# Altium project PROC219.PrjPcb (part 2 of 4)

## Sheet PROC219_PLC.SchDoc
size 431 x 279 mm; Date: Not shown in title block; ApprovedBy: Not shown in title block; CheckedBy: Not shown in title block; Author: Not shown in title block; CompanyName: Not shown in title block; Engineer: Not shown in title block; Organization: Not shown in title block; Address1: Not shown in title block; Address2: Not shown in title block; Address3: Not shown in title block; Address4: Not shown in title block; DocumentNumber: 1; Revision: Use project parameter SCH_Rev; SheetNumber: 5; SheetTotal: 16; PageSetup: Record=PageOptions¦CenterHorizontal=True¦CenterVertical=True¦PrintScale=1.00¦XCorrection=1.00¦YCorrection=1.00¦PrintKind=0¦BorderSize=5000000¦LeftOffset=0¦BottomOffset=0¦Orientation=2¦PaperLength=1000¦PaperWidth=1000¦Scale=100¦PaperSource=15¦PrintQuality=600¦MediaType=1¦DitherType=10¦PaperKind=Letter¦PrintScaleMode=1
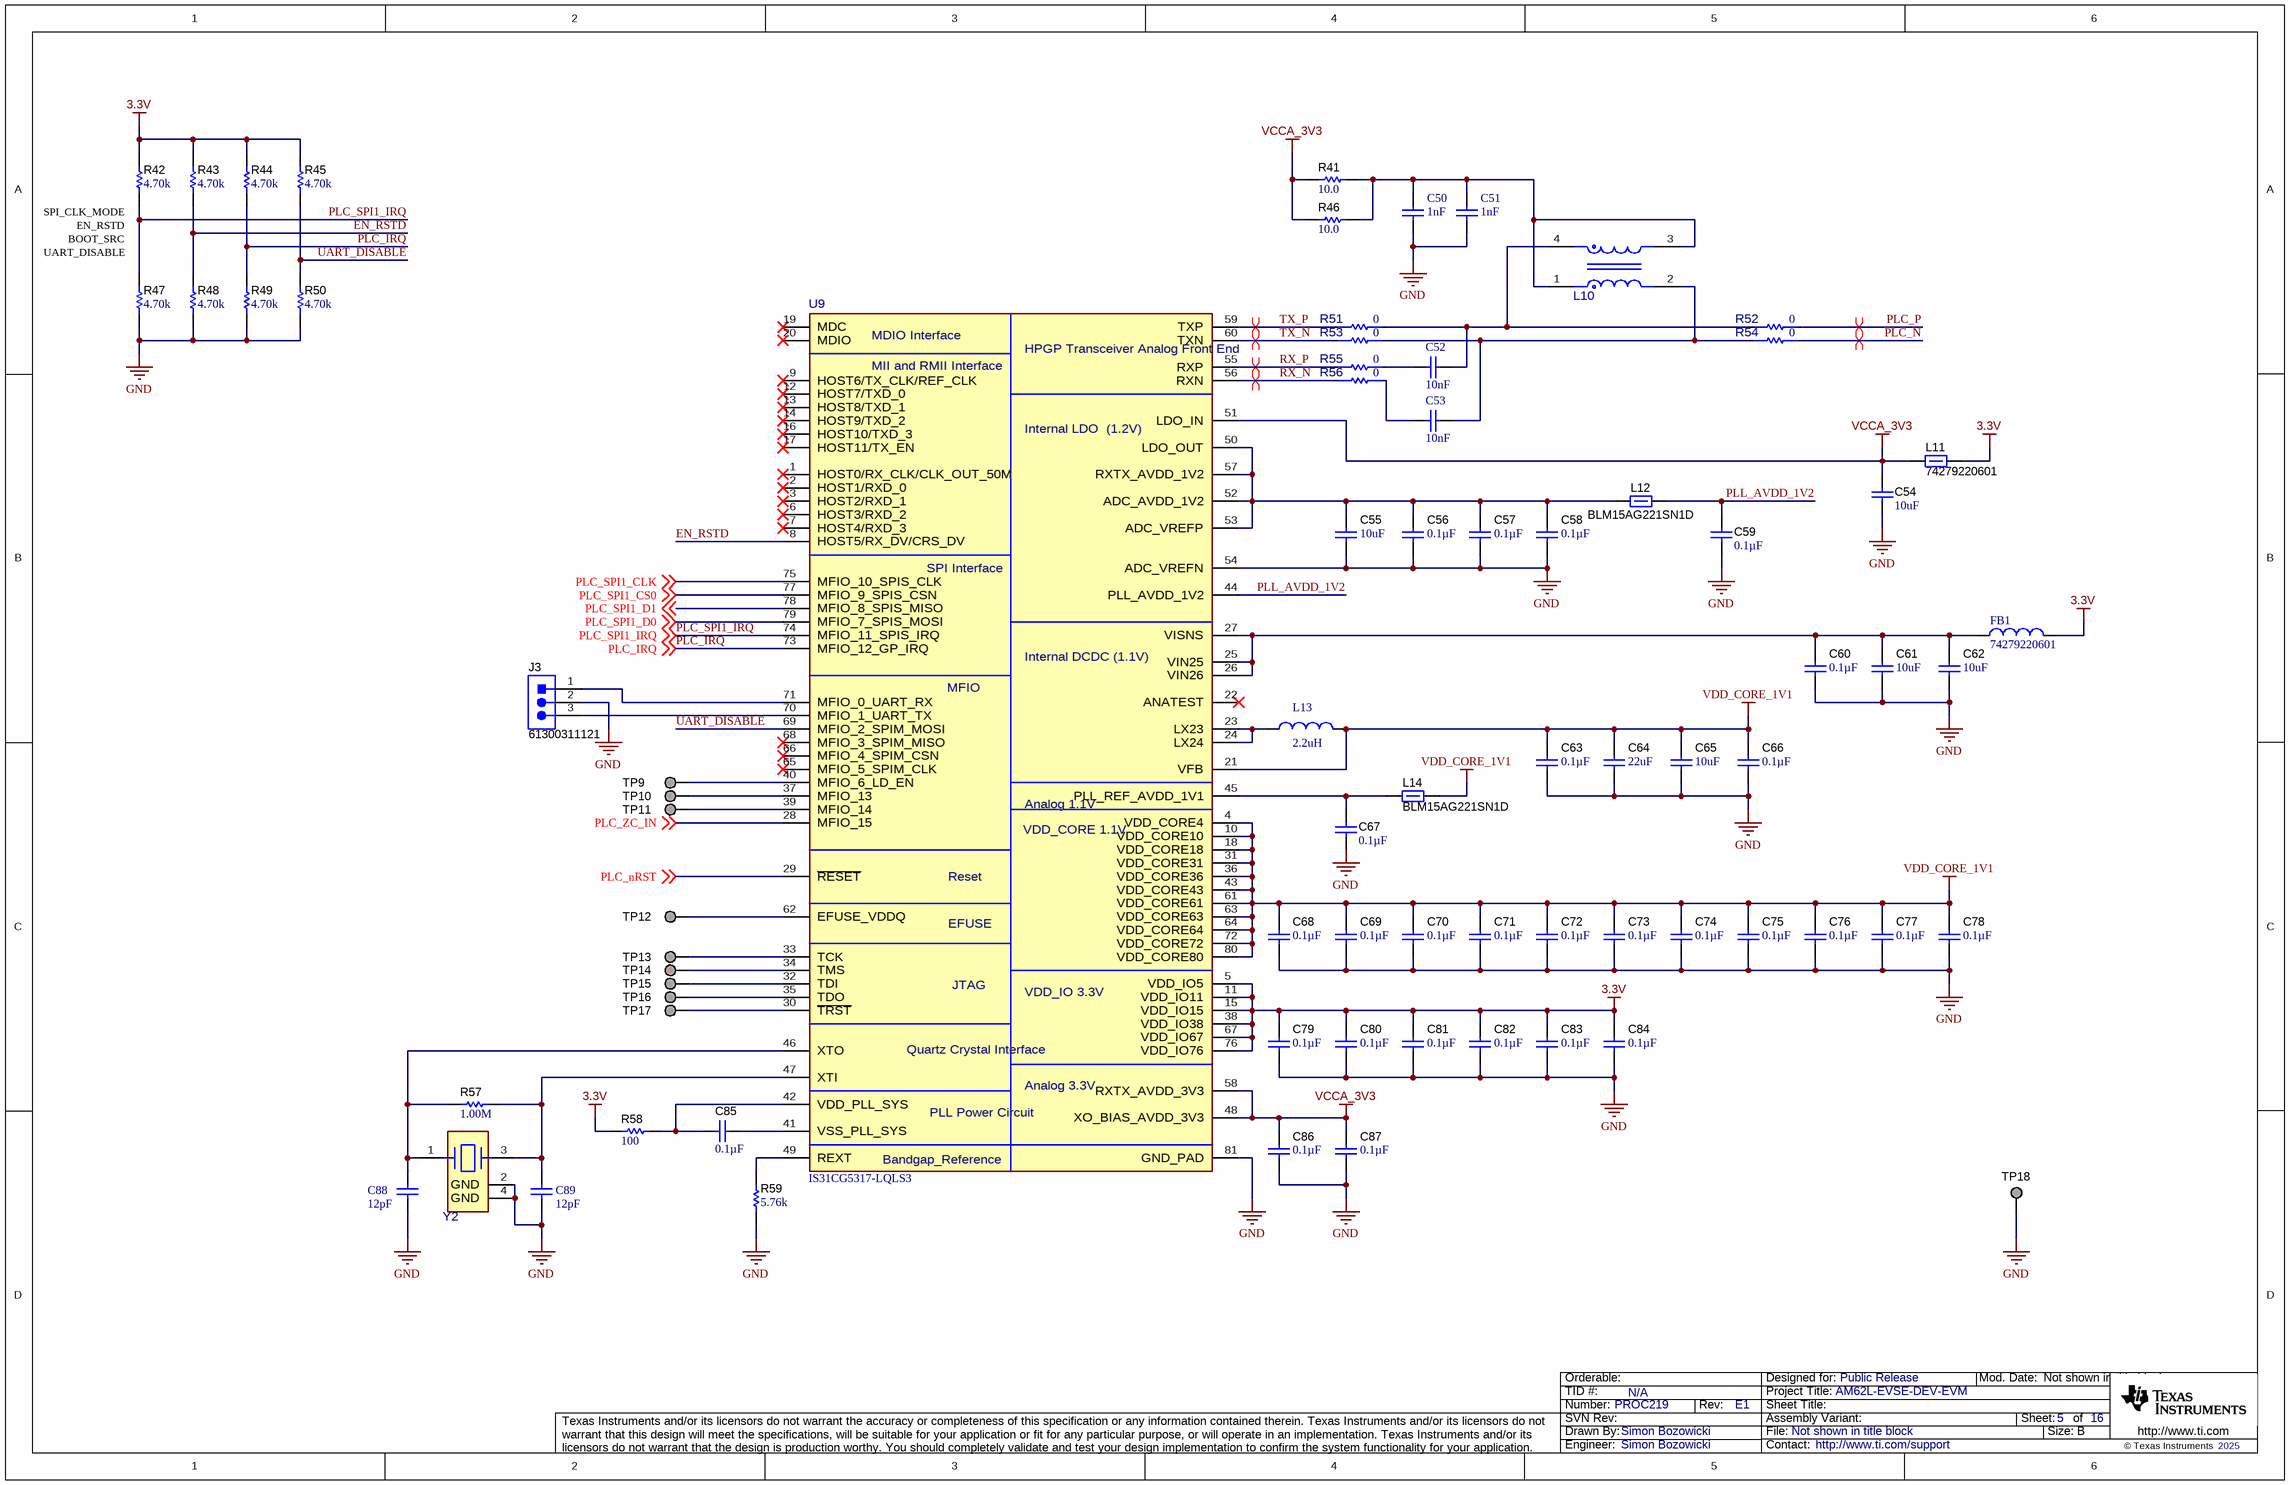
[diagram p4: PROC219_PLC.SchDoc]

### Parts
C50  value 1nF  [WCAP-CSGP_0402_L1W0.5H0.5]  (hidden comment: 885012205061)
C51  value 1nF  [WCAP-CSGP_0402_L1W0.5H0.5]  (hidden comment: 885012205061)
C52  value 10nF  [WCAP-CSGP_0402_L1W0.5H0.5]  (hidden comment: 885012205050)
C53  value 10nF  [WCAP-CSGP_0402_L1W0.5H0.5]  (hidden comment: 885012205050)
C54  ValueDisplayed: 10uF  [0603]  (hidden comment: C1608X5R1E106M080AC)
C55  ValueDisplayed: 10uF  [0603]  (hidden comment: C1608X5R1E106M080AC)
C56  ValueDisplayed: 0.1µF  [0402]  (hidden comment: CC0402KRX7R8BB104)
C57  ValueDisplayed: 0.1µF  [0402]  (hidden comment: CC0402KRX7R8BB104)
C58  ValueDisplayed: 0.1µF  [0402]  (hidden comment: CC0402KRX7R8BB104)
C59  ValueDisplayed: 0.1µF  [0402]  (hidden comment: CC0402KRX7R8BB104)
C60  ValueDisplayed: 0.1µF  [0402]  (hidden comment: CC0402KRX7R8BB104)
C61  ValueDisplayed: 10uF  [0603]  (hidden comment: C1608X5R1E106M080AC)
C62  ValueDisplayed: 10uF  [0603]  (hidden comment: C1608X5R1E106M080AC)
C63  ValueDisplayed: 0.1µF  [0402]  (hidden comment: CC0402KRX7R8BB104)
C64  ValueDisplayed: 22uF  [0805_HV]  (hidden comment: C2012X7S1A226M125AC)
C65  ValueDisplayed: 10uF  [0603]  (hidden comment: C1608X5R1E106M080AC)
C66  ValueDisplayed: 0.1µF  [0402]  (hidden comment: CC0402KRX7R8BB104)
C67  ValueDisplayed: 0.1µF  [0402]  (hidden comment: CC0402KRX7R8BB104)
C68  ValueDisplayed: 0.1µF  [0402]  (hidden comment: CC0402KRX7R8BB104)
C69  ValueDisplayed: 0.1µF  [0402]  (hidden comment: CC0402KRX7R8BB104)
C70  ValueDisplayed: 0.1µF  [0402]  (hidden comment: CC0402KRX7R8BB104)
C71  ValueDisplayed: 0.1µF  [0402]  (hidden comment: CC0402KRX7R8BB104)
C72  ValueDisplayed: 0.1µF  [0402]  (hidden comment: CC0402KRX7R8BB104)
C73  ValueDisplayed: 0.1µF  [0402]  (hidden comment: CC0402KRX7R8BB104)
C74  ValueDisplayed: 0.1µF  [0402]  (hidden comment: CC0402KRX7R8BB104)
C75  ValueDisplayed: 0.1µF  [0402]  (hidden comment: CC0402KRX7R8BB104)
C76  ValueDisplayed: 0.1µF  [0402]  (hidden comment: CC0402KRX7R8BB104)
C77  ValueDisplayed: 0.1µF  [0402]  (hidden comment: CC0402KRX7R8BB104)
C78  ValueDisplayed: 0.1µF  [0402]  (hidden comment: CC0402KRX7R8BB104)
C79  ValueDisplayed: 0.1µF  [0402]  (hidden comment: CC0402KRX7R8BB104)
C80  ValueDisplayed: 0.1µF  [0402]  (hidden comment: CC0402KRX7R8BB104)
C81  ValueDisplayed: 0.1µF  [0402]  (hidden comment: CC0402KRX7R8BB104)
C82  ValueDisplayed: 0.1µF  [0402]  (hidden comment: CC0402KRX7R8BB104)
C83  ValueDisplayed: 0.1µF  [0402]  (hidden comment: CC0402KRX7R8BB104)
C84  ValueDisplayed: 0.1µF  [0402]  (hidden comment: CC0402KRX7R8BB104)
C85  ValueDisplayed: 0.1µF  [0402]  (hidden comment: CC0402KRX7R8BB104)
C86  ValueDisplayed: 0.1µF  [0402]  (hidden comment: CC0402KRX7R8BB104)
C87  ValueDisplayed: 0.1µF  [0402]  (hidden comment: CC0402KRX7R8BB104)
C88  value 12pF  [WCAP-CSRF_0402_L1W0.5H0.5]  (hidden comment: 885392005127)
C89  value 12pF  [WCAP-CSRF_0402_L1W0.5H0.5]  (hidden comment: 885392005127)
FB1  74279220601  [WE-MPSB_0805_L2W1.2H0.9]
J3  61300311121  [WURTH_61300311121]
L10  DLW43SH110XK2L  [FP-DLW43SH110XK2L_1812-MFG]  (value not drawn)
L11  74279220601  [0805_HV]
L12  BLM15AG221SN1D  [0402]
L13  value 2.2uH  [WE-PMCI_1210_L3.2W2.5H1.2]  (hidden comment: 74479299222)
L14  BLM15AG221SN1D  [0402]
R41  ValueDisplayed: 10.0  [0603]  (hidden comment: RC0603FR-0710RL)
R42  ValueDisplayed: 4.70k  [0402]  (hidden comment: ERJ-2RKF4701X)
R43  ValueDisplayed: 4.70k  [0402]  (hidden comment: ERJ-2RKF4701X)
R44  ValueDisplayed: 4.70k  [0402]  (hidden comment: ERJ-2RKF4701X)
R45  ValueDisplayed: 4.70k  [0402]  (hidden comment: ERJ-2RKF4701X)
R46  ValueDisplayed: 10.0  [0603]  (hidden comment: RC0603FR-0710RL)
R47  ValueDisplayed: 4.70k  [0402]  (hidden comment: ERJ-2RKF4701X)
R48  ValueDisplayed: 4.70k  [0402]  (hidden comment: ERJ-2RKF4701X)
R49  ValueDisplayed: 4.70k  [0402]  (hidden comment: ERJ-2RKF4701X)
R50  ValueDisplayed: 4.70k  [0402]  (hidden comment: ERJ-2RKF4701X)
R51  value 0  [FP-CRG0402ZR_0402-IPC_C]  (hidden comment: CRG0402ZR)
R52  value 0  [FP-CRG0402ZR_0402-IPC_C]  (hidden comment: CRG0402ZR)
R53  value 0  [FP-CRG0402ZR_0402-IPC_C]  (hidden comment: CRG0402ZR)
R54  value 0  [FP-CRG0402ZR_0402-IPC_C]  (hidden comment: CRG0402ZR)
R55  value 0  [FP-CRG0402ZR_0402-IPC_C]  (hidden comment: CRG0402ZR)
R56  value 0  [FP-CRG0402ZR_0402-IPC_C]  (hidden comment: CRG0402ZR)
R57  ValueDisplayed: 1.00M  [0402]  (hidden comment: RC0402FR-071ML)
R58  ValueDisplayed: 100  [0402]  (hidden comment: ERJ-2RKF1000X)
R59  ValueDisplayed: 5.76k  [0402]  (hidden comment: CRCW04025K76FKED)
TP9  TP_SM_1MM  [TP_SM_1MM]  (value not drawn)  (no BOM)
TP10  TP_SM_1MM  [TP_SM_1MM]  (value not drawn)  (no BOM)
TP11  TP_SM_1MM  [TP_SM_1MM]  (value not drawn)  (no BOM)
TP12  TP_SM_1MM  [TP_SM_1MM]  (value not drawn)  (no BOM)
TP13  TP_SM_1MM  [TP_SM_1MM]  (value not drawn)  (no BOM)
TP14  TP_SM_1MM  [TP_SM_1MM]  (value not drawn)  (no BOM)
TP15  TP_SM_1MM  [TP_SM_1MM]  (value not drawn)  (no BOM)
TP16  TP_SM_1MM  [TP_SM_1MM]  (value not drawn)  (no BOM)
TP17  TP_SM_1MM  [TP_SM_1MM]  (value not drawn)  (no BOM)
TP18  TP_SM_1MM  [TP_SM_1MM]  (value not drawn)  (no BOM)
U9  IS31CG5317-LQLS3  [FP-IS31CG5317-LQLS3_LQFP80-MFG]
Y2  ABM8W-25.0000MHZ-8-D1X-T3  [FP-ABM8W-25.0000MHZ-8-D1X-T3_SMD4-MFG]  (value not drawn)

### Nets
3.3V: C79.1 C80.1 C81.1 C82.1 C83.1 C84.1 FB1.2 L11.2 R42.2 R43.2 R44.2 R45.2 R58.2 U9.5(VDD_IO5) U9.11(VDD_IO11) U9.15(VDD_IO15) U9.38(VDD_IO38) U9.67(VDD_IO67) U9.76(VDD_IO76)
GND: C50.2 C51.2 C54.1 C55.2 C56.2 C57.2 C58.2 C59.1 C60.2 C61.2 C62.2 C63.2 C64.2 C65.2 C66.2 C67.2 C68.2 C69.2 C70.2 C71.2 C72.2 C73.2 C74.2 C75.2 C76.2 C77.2 C78.2 C79.2 C80.2 C81.2 C82.2 C83.2 C84.2 C86.2 C87.2 C88.1 C89.1 J3.2 R47.1 R48.1 R49.1 R50.1 R59.1 TP18.1 U9.54(ADC_VREFN) U9.81(GND_PAD) Y2.2(GND) Y2.4(GND)
VCCA_3V3: C54.2 C86.1 C87.1 L11.1 R41.1 R46.1 U9.48(XO_BIAS_AVDD_3V3) U9.51(LDO_IN) U9.58(RXTX_AVDD_3V3)
VDD_CORE_1V1: C63.1 C64.1 C65.1 C66.1 C68.1 C69.1 C70.1 C71.1 C72.1 C73.1 C74.1 C75.1 C76.1 C77.1 C78.1 L13.2 L14.2 U9.4(VDD_CORE4) U9.10(VDD_CORE10) U9.18(VDD_CORE18) U9.21(VFB) U9.31(VDD_CORE31) U9.36(VDD_CORE36) U9.43(VDD_CORE43) U9.61(VDD_CORE61) U9.63(VDD_CORE63) U9.64(VDD_CORE64) U9.72(VDD_CORE72) U9.80(VDD_CORE80)
EN_RSTD: R43.1 R48.2 U9.8(HOST5/RX_DV/CRS_DV)
PLC_IRQ: R44.1 R49.2 U9.73(MFIO_12_GP_IRQ) ; off-sheet PLC_IRQ
PLC_N: R54.1
PLC_nRST: U9.29(~{RESET}) ; off-sheet PLC_nRST
PLC_P: R52.1
PLC_SPI1_CLK: U9.75(MFIO_10_SPIS_CLK) ; off-sheet PLC_SPI1_CLK
PLC_SPI1_CS0: U9.77(MFIO_9_SPIS_CSN) ; off-sheet PLC_SPI1_CS0
PLC_SPI1_D0: U9.79(MFIO_7_SPIS_MOSI) ; off-sheet PLC_SPI1_D0
PLC_SPI1_D1: U9.78(MFIO_8_SPIS_MISO) ; off-sheet PLC_SPI1_D1
PLC_SPI1_IRQ: R42.1 R47.2 U9.74(MFIO_11_SPIS_IRQ) ; off-sheet PLC_SPI1_IRQ
PLC_ZC_IN: U9.28(MFIO_15) ; off-sheet PLC_ZC_IN
PLL_AVDD_1V2: C59.2 L12.2 U9.44(PLL_AVDD_1V2)
RX_N: R56.2 U9.56(RXN)
RX_P: R55.2 U9.55(RXP)
TX_N: R53.2 U9.60(TXN)
TX_P: R51.2 U9.59(TXP)
UART_DISABLE: R45.1 R50.2 U9.69(MFIO_2_SPIM_MOSI)
NetC50_1: C50.1 C51.1 L10.1 L10.3 R41.2 R46.2
NetC52_1: C52.1 L10.4 R51.1 R52.2
NetC52_2: C52.2 R55.1
NetC53_1: C53.1 L10.2 R53.1 R54.2
NetC53_2: C53.2 R56.1
NetC55_1: C55.1 C56.1 C57.1 C58.1 L12.1 U9.50(LDO_OUT) U9.52(ADC_AVDD_1V2) U9.53(ADC_VREFP) U9.57(RXTX_AVDD_1V2)
NetC60_1: C60.1 C61.1 C62.1 FB1.1 U9.25(VIN25) U9.26(VIN26) U9.27(VISNS)
NetC67_1: C67.1 L14.1 U9.45(PLL_REF_AVDD_1V1)
NetC85_1: C85.1 U9.41(VSS_PLL_SYS)
NetC85_2: C85.2 R58.1 U9.42(VDD_PLL_SYS)
NetC88_2: C88.2 R57.1 U9.46(XTO) Y2.1
NetC89_2: C89.2 R57.2 U9.47(XTI) Y2.3
NetJ3_1: J3.1 U9.71(MFIO_0_UART_RX)
NetJ3_3: J3.3 U9.70(MFIO_1_UART_TX)
NetL13_1: L13.1 U9.23(LX23) U9.24(LX24)
NetR59_2: R59.2 U9.49(REXT)
NetTP9_1: TP9.1 U9.40(MFIO_6_LD_EN)
NetTP10_1: TP10.1 U9.37(MFIO_13)
NetTP11_1: TP11.1 U9.39(MFIO_14)
NetTP12_1: TP12.1 U9.62(EFUSE_VDDQ)
NetTP13_1: TP13.1 U9.33(TCK)
NetTP14_1: TP14.1 U9.34(TMS)
NetTP15_1: TP15.1 U9.32(TDI)
NetTP16_1: TP16.1 U9.35(TDO)
NetTP17_1: TP17.1 U9.30(~{TRST})

Not connected (* = marked no-connect by the designer): U9 1(HOST0/RX_CLK/CLK_OUT_50M)* 2(HOST1/RXD_0)* 3(HOST2/RXD_1)* 6(HOST3/RXD_2)* 7(HOST4/RXD_3)* 9(HOST6/TX_CLK/REF_CLK)* 12(HOST7/TXD_0)* 13(HOST8/TXD_1)* 14(HOST9/TXD_2)* 16(HOST10/TXD_3)* 17(HOST11/TX_EN)* 19(MDC)* 20(MDIO)* 22(ANATEST)* 65(MFIO_5_SPIM_CLK)* 66(MFIO_4_SPIM_CSN)* 68(MFIO_3_SPIM_MISO)*

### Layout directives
differential pair: PLC_N, PLC_P, RX_N, RX_P, TX_N, TX_P

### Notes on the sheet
- (near R42) SPI_CLK_MODE
- (near R42) EN_RSTD
- BOOT_SRC
- (near R47) UART_DISABLE

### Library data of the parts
C50 C51 = CMP-0115372-1: WCAP-CSGP Multilayer Ceramic Chip Capacitor, General Purpose, size 0402, X7R, 1nF, 50VDC; Manufacturer: Wurth Elektronik; Capacitance Tolerance: +/-10%; Dissipation Factor: 2.5%; Insulation Resistance: 10GOhm; Rated Voltage (DC): 50V; Technical Reference: X7R0402102K050DFCT10000
C52 C53 = CMP-0052806-1: WCAP-CSGP Multilayer Ceramic Chip Capacitor, General Purpose, size 0402, X7R, 10nF, 25VDC; Manufacturer: Wurth Elektronik; Capacitance Tolerance: +/-10%; Dissipation Factor: 3.5%; Insulation Resistance: 10GOhm; Rated Voltage (DC): 25V; Technical Reference: X7R0402103K025DFCT10000
C54 C55 C61 C62 C65 = CMP-0007007-5: CAP, CERM, 10 uF, 25 V, +/- 20%, X5R, 0603; Manufacturer: TDK; TaMin_C: -55°C; ESR_ohm: 4.639m; Polarized: N; SizeAreaWB_mm2: 4.68; Value1: 0.004639 ohm; U/M: EA; Value: 10uF; TaMax_C: 85°C; SizeZ_mm: 1; SizeX_mm: 1.6; SizeY_mm: 0.8; Value2: 25V; SizeArea_mm2: 1.28; Cap_F: 10µF; IRMS_A: 2.41407A; AEC Category: Q200
C56-C60 C63 C66-C87 = CMP-0860555-1: CAP, CERM, 0.1 µF, 25 V,+/- 10%, X7R, 0402; Manufacturer: Yageo; SizeArea_mm2: 0.5; AEC Qualified: N; SizeX_mm: 1; U/M: EA; Value: 0.1uF; TaMin_C: -55°C; VDC_V: 25V; SizeZ_mm: 0.6; Cap_F: 100nF; TaMax_C: 125°C; SizeAreaWB_mm2: 3; AEC Category: Q200
C64 = CMP-0007890-2: CAP, CERM, 22 uF, 10 V, +/- 20%, X7S, 0805; Manufacturer: TDK; TaMin_C: -55°C; ESR_ohm: 2.05m; Polarized: N; SizeAreaWB_mm2: 6.75; Value1: 0.00205 ohm; U/M: EA; Value: 22uF; TaMax_C: 125°C; SizeZ_mm: 1.45; SizeX_mm: 2; SizeY_mm: 1.25; Cap_Case: 0805; Value2: 10V; SizeArea_mm2: 2.5; Cap_F: 22µF; IRMS_A: 4.55587A; AEC Category: Q200
C88 C89 = CMP-0105275-1: WCAP-CSRF Multilayer Ceramic Chip Capacitor, High Frequency, size 0402, NP0 Class I, 12pF, 50VDC; Manufacturer: Wurth Elektronik; Capacitance Tolerance: +/-2%; Insulation Resistance: 10GOhm; Q Factor: 640; Rated Voltage (DC): 50V; Technical Reference: NP00402120G050DFCT1R000
FB1 = CMP-03913-52738340-1: 74279220601 Ferrite Beads Multi-Layer High Current 600Ohm 25% 100MHz 2.1A 0.08Ohm DCR 0805 Automotive T/R; Manufacturer: Wurth Elektronik; DC Resistance (DCR): 43mΩ; Number of Lines: 1; Value: 600Ω
J3 = CMP-0054796-4: Header, 2.54 mm, 3x1, Gold, TH; Manufacturer: Wurth Elektronik; Green_REACh: Passed; CT: FALSE; CNHeader: TRUE; Green_Lifecycle: Active
L10 = CMP-0124832-1: 2 Line Common Mode Choke Surface Mount 360mA DCR 500mOhm; Manufacturer: Murata; AEC Grade: Grade 1; AEC Qualified: Yes; DCR_ohm: 0.5; Ind_H: 11µH; SizeZ_mm: 2.8mm; Shrouded: true; Test Frequency: 100kHz; Tolerance_%: +50/-30%
L11 = CMP-0003136-1: Ferrite Bead, 600 ohm @ 100 MHz, 2.1 A, 0805; Manufacturer: Wurth Elektronik; Ztyp@1GHz_Ohm: 101.062; ZTyp@100MHz_Ohm: 600; SizeAreaWB_mm2: 6.75; DCR_ohm: 0.043; Value1: 0.043 ohm; Value: 600 ohm; Imax_A: 2.1A; SizeZ_mm: 1.45; SizeX_mm: 2; SizeY_mm: 1.25; SizeArea_mm2: 2.5
L12 L14 = CMP-0003312-1: Ferrite Bead, 220 ohm @ 100 MHz, 0.45 A, 0402; Manufacturer: MuRata; ZTyp@100MHz_Ohm: 220; SizeAreaWB_mm2: 3; DCR_ohm: 2.9d; Value1: 0.29 ohm; Value: 220 ohm; Imax_A: 4.5dA; SizeZ_mm: 0.6; SizeX_mm: 1; SizeY_mm: 0.5; Value2: 0.45A
L13 = CMP-0100963-1: WE-PMCI SMT Power Molded Chip Inductor, size 1210, 2.2uH, 4.5A, 75mOhm; Manufacturer: Wurth Elektronik; DC Resistance: 70mOhm; Saturation Current: 4.8A; Self Resonant Frequency: 35MHz; Type: High Saturation Current
R41 R46 = CMP-0022751-4: RES, 10.0, 1%, 0.1 W, 0603; Manufacturer: Yageo; Power_W: 100mW; TempCo: 100 ppm/C; Value_Code: 10R0; Value: 10.0; EIA_Code: E96; Res_ohm: 10; SizeX_mm: 1.6; SizeY_mm: 0.8; SizeZ_mm: 1; Value2: 0.1W; SizeArea_mm2: 1.28; AEC Qualified: N; VDC_V: 75V; AEC Category: Q200; SizeAreaWB_mm2: 4.68
R42-R45 R47-R50 = CMP-0026700-1: RES, 4.70 k, 1%, 0.1 W, 0402; Manufacturer: Panasonic; Power_W: 100mW; TempCo: 100 ppm/C; Value_Code: 4k70; U/M: EA; Value: 4.70k; Res_ohm: 4.7k; SizeX_mm: 1; SizeY_mm: 0.5; SizeZ_mm: 0.6; Value2: 0.1W; VDC_V: 50V; AEC Category: Q200
R51-R56 = CMP-0095664-1: Jumper 0.063W, 1/16W Chip Resistor 0402 (1005 Metric) - Thick Film; Manufacturer: TE Connectivity; SizeZ_mm: 0.4mm; VDC_V: 50V; TempCo: 200ppm/°C; Power_W: 62.5mW; AEC Qualified: No
R57 = CMP-0026727-1: RES, 1.00 M, 1%, 0.063 W, 0402; Manufacturer: Yageo America; Power_W: 63mW; TempCo: 100 ppm/C; Value_Code: 1M00; U/M: EA; Value: 1.00Meg; EIA_Code: E96; Res_ohm: 1M; SizeX_mm: 1; SizeY_mm: 0.5; SizeZ_mm: 0.6; Value2: 0.063W; AEC Category: Q200
R58 = CMP-0026656-1: RES, 100, 1%, 0.1 W, 0402; Manufacturer: Panasonic; Power_W: 100mW; TempCo: 100 ppm/C; Value_Code: 100R; U/M: EA; Value: 100; EIA_Code: E96; SizeX_mm: 1; SizeY_mm: 0.5; SizeZ_mm: 0.6; Value2: 0.1W; VDC_V: 50V; AEC Category: Q200
R59 = CMP-0026468-2: RES, 5.76 k, 1%, 0.063 W, AEC-Q200 Grade 0, 0402; Manufacturer: Vishay-Dale; Power_W: 63mW; TempCo: 100 ppm/C; Value_Code: 5k76; Value: 5.76k; EIA_Code: E96; SizeX_mm: 1; SizeY_mm: 0.5; SizeZ_mm: 0.6; Value2: 0.063W; AEC Qualified: Y; VDC_V: 50V; AEC Category: Q200; AEC Grade: 0
TP9-TP18 = CMP-0003825-1: 1mm Test Point, SMT; Manufacturer: Any
U9 = CMP-0124871-1: Manufacturer: Lumissil Microsystems; SizeZ_mm: 1.6mm; Standoff Height: 0.05mm
Y2 = CMP-0124828-1: Crystal 25MHz ±10ppm (Tol) ±20ppm (Stability) 8pF FUND 100Ohm 4-Pin SMD T/R; Manufacturer: Abracon; SizeZ_mm: 0.75mm; AEC Qualified: No; Esr: 50

## Sheet PROC219_Pilot_Interface.SchDoc
size 431 x 279 mm; Date: Not shown in title block; ApprovedBy: Not shown in title block; CheckedBy: Not shown in title block; Author: Not shown in title block; CompanyName: Not shown in title block; Engineer: Not shown in title block; Organization: Not shown in title block; Address1: Not shown in title block; Address2: Not shown in title block; Address3: Not shown in title block; Address4: Not shown in title block; DocumentNumber: 1; Revision: Use project parameter SCH_Rev; SheetNumber: 6; SheetTotal: 16; PageSetup: Record=PageOptions¦CenterHorizontal=True¦CenterVertical=True¦PrintScale=1.00¦XCorrection=1.00¦YCorrection=1.00¦PrintKind=0¦BorderSize=5000000¦LeftOffset=0¦BottomOffset=0¦Orientation=2¦PaperLength=1000¦PaperWidth=1000¦Scale=100¦PaperSource=15¦PrintQuality=600¦MediaType=1¦DitherType=10¦PaperKind=Letter¦PrintScaleMode=1
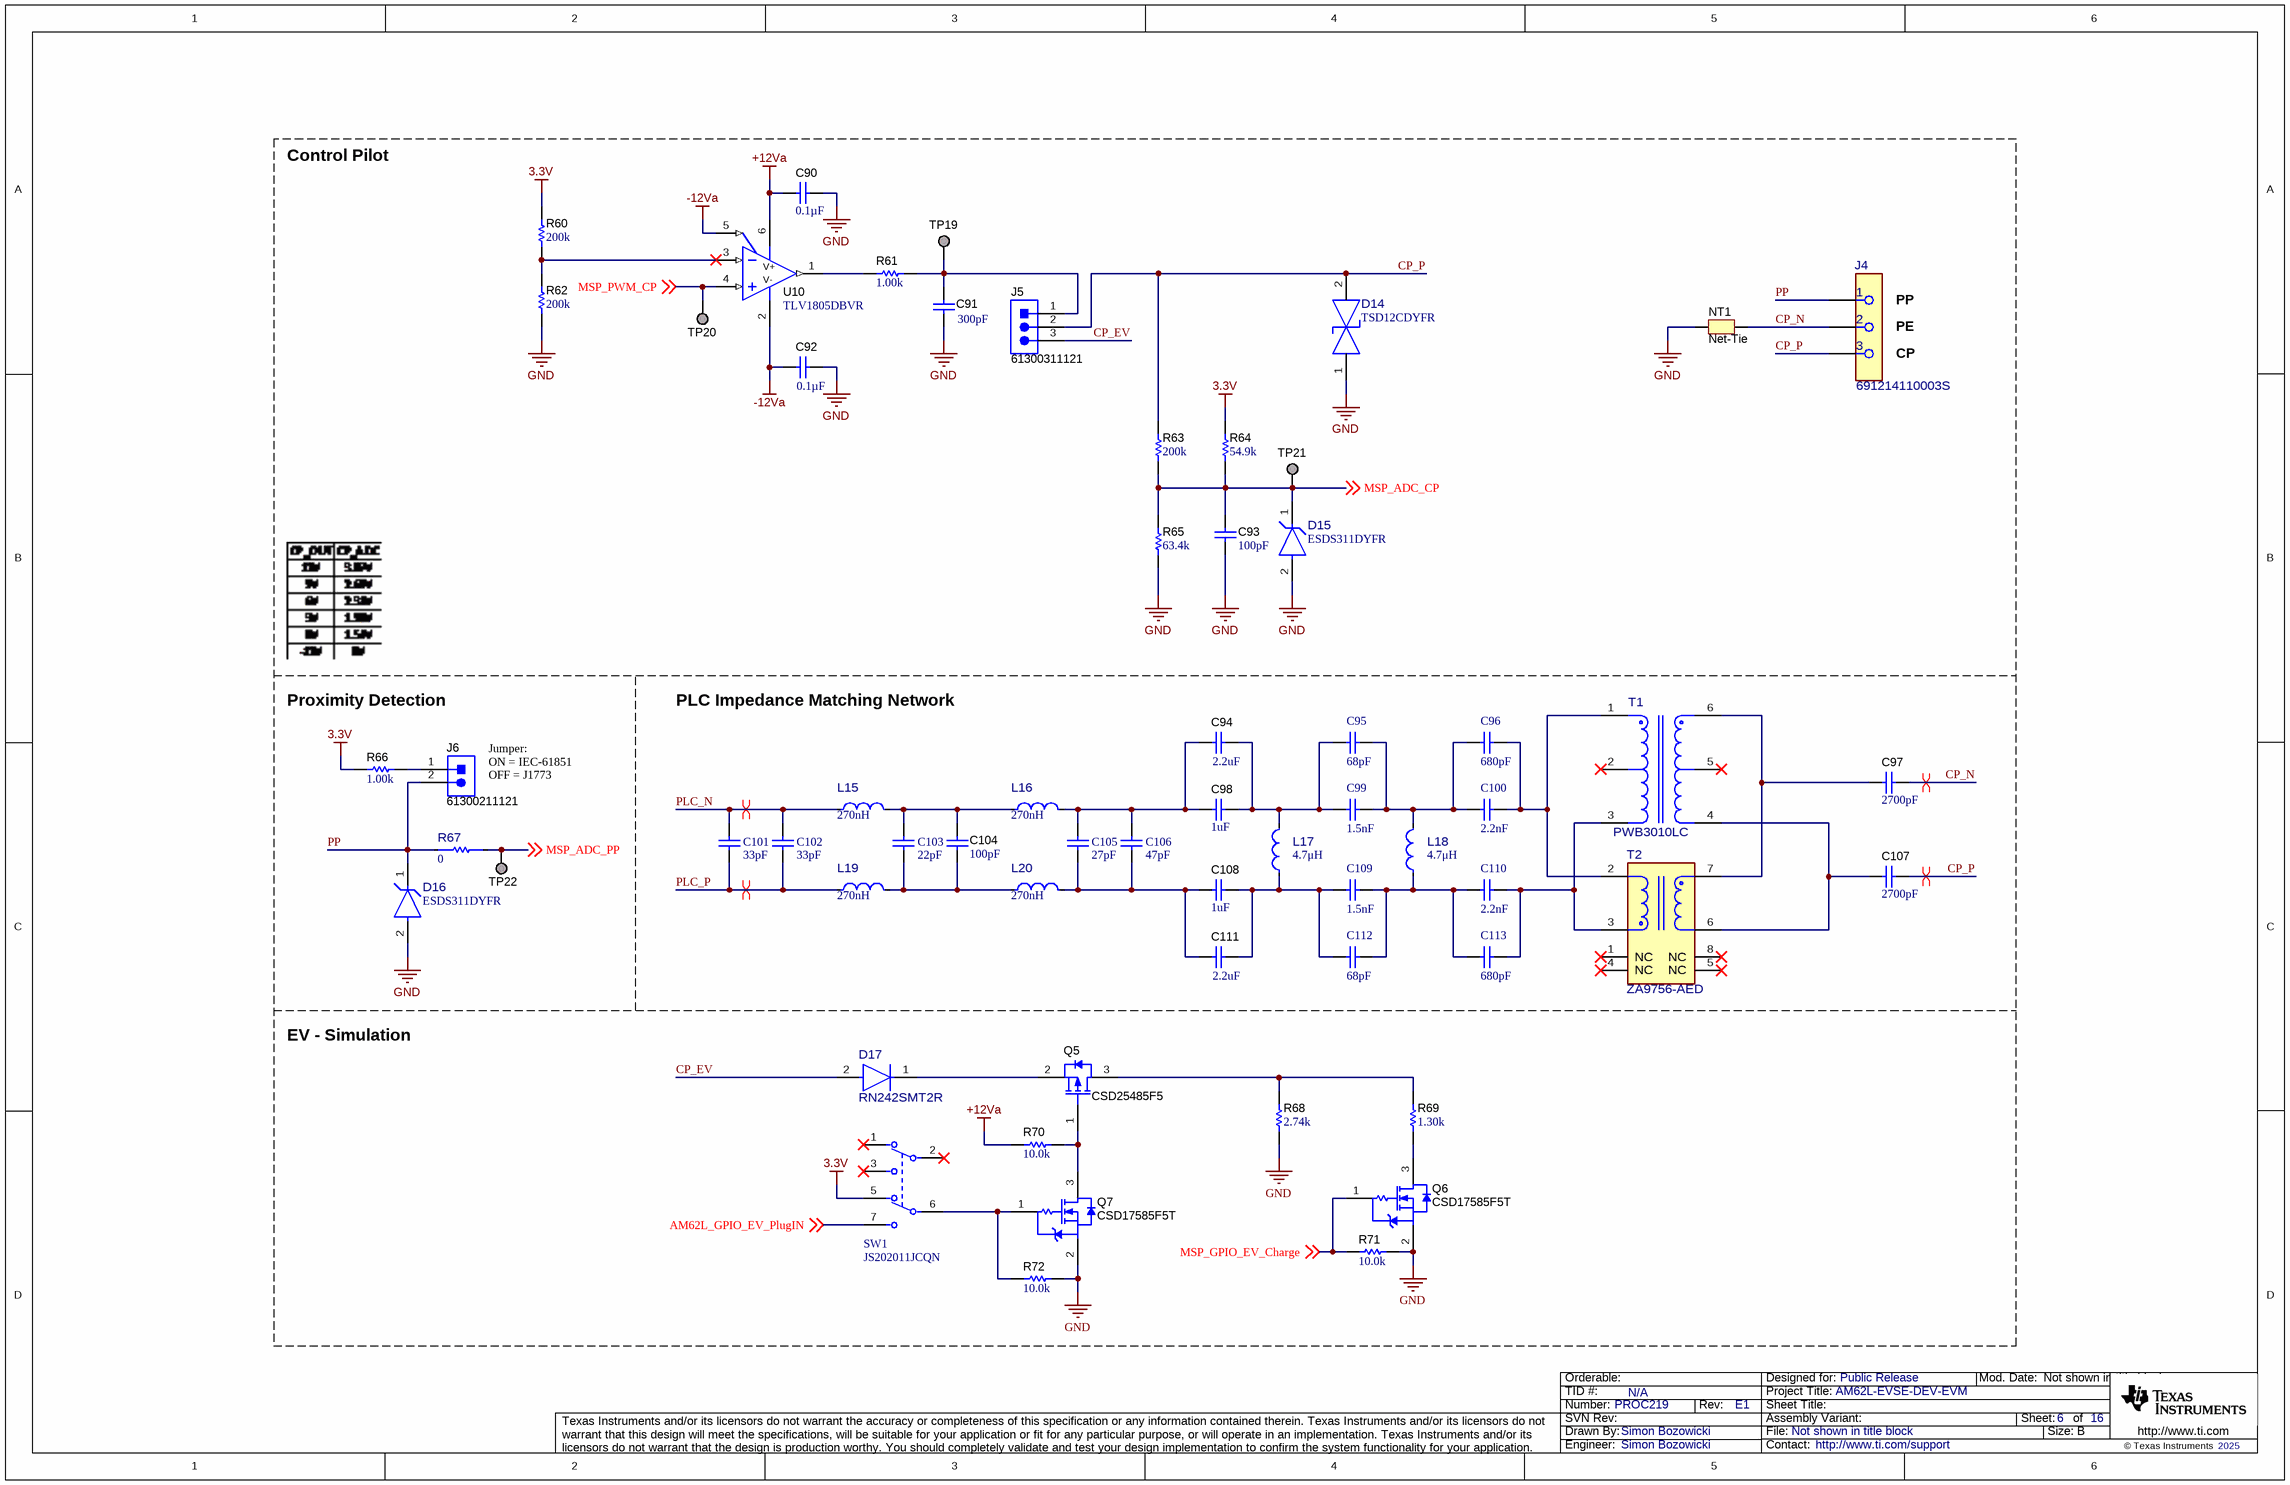
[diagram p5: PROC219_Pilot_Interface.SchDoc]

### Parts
C90  ValueDisplayed: 0.1µF  [0402]  (hidden comment: CC0402KRX7R8BB104)
C91  ValueDisplayed: 300pF  [0402]  (hidden comment: GCM1555C1H301JA16D)
C92  ValueDisplayed: 0.1µF  [0402]  (hidden comment: CC0402KRX7R8BB104)
C93  ValueDisplayed: 100pF  [0402]  (hidden comment: 04025A101FAT2A)
C94  ValueDisplayed: 2.2uF  [0402]  (hidden comment: C1005X5R1C225K050BC)
C95  value 68pF  [WCAP-CSGP_0402_L1W0.5H0.5]  (hidden comment: 885012005060)
C96  value 680pF  [WCAP-CSGP_0402_L1W0.5H0.5]  (hidden comment: 885012205060)
C97  ValueDisplayed: 2700pF  [0402]  (hidden comment: CL05B272KB5NNNC)
C98  ValueDisplayed: 1uF  [0402]  (hidden comment: C1005X7S1A105K050BC)
C99  value 1.5nF  [WCAP-CSGP_0402_L1W0.5H0.5]  (hidden comment: 885012205062)
C100  value 2.2nF  [WCAP-CSGP_0402_L1W0.5H0.5]  (hidden comment: 885012205063)
C101  value 33pF  [WCAP-CSGP_0402_L1W0.5H0.5]  (hidden comment: 885012005058)
C102  value 33pF  [WCAP-CSGP_0402_L1W0.5H0.5]  (hidden comment: 885012005058)
C103  value 22pF  [WCAP-CSRF_0402_L1W0.5H0.5]  (hidden comment: 885392005114)
C104  ValueDisplayed: 100pF  [0402]  (hidden comment: 04025A101FAT2A)
C105  value 27pF  [WCAP-CSRF_0402_L1W0.5H0.5]  (hidden comment: 885392005116)
C106  value 47pF  [WCAP-CSGP_0402_L1W0.5H0.5]  (hidden comment: 885012005059)
C107  ValueDisplayed: 2700pF  [0402]  (hidden comment: CL05B272KB5NNNC)
C108  ValueDisplayed: 1uF  [0402]  (hidden comment: C1005X7S1A105K050BC)
C109  value 1.5nF  [WCAP-CSGP_0402_L1W0.5H0.5]  (hidden comment: 885012205062)
C110  value 2.2nF  [WCAP-CSGP_0402_L1W0.5H0.5]  (hidden comment: 885012205063)
C111  ValueDisplayed: 2.2uF  [0402]  (hidden comment: C1005X5R1C225K050BC)
C112  value 68pF  [WCAP-CSGP_0402_L1W0.5H0.5]  (hidden comment: 885012005060)
C113  value 680pF  [WCAP-CSGP_0402_L1W0.5H0.5]  (hidden comment: 885012205060)
D14  TSD12CDYFR  [DYF0002A-CA-MFG]
D15  ESDS311DYFR  [DYF0002A-MFG]
D16  ESDS311DYFR  [DYF0002A-MFG]
D17  RN242SMT2R  [FP-RN242SMT2R_EMD2-MFG]
J4  691214110003S  [FP-691214110003S_CONN_TERM_BLK_3-MFG]
J5  61300311121  [WURTH_61300311121]
J6  61300211121  [WURTH_61300211121]
L15  value 270nH  [FP-LQW18ANR27G80D_0603 (1608)-MFG]  (hidden comment: LQW18ANR27G80D)
L16  value 270nH  [FP-LQW18ANR27G80D_0603 (1608)-MFG]  (hidden comment: LQW18ANR27G80D)
L17  value 4.7μH  [FP-LQM21PN4R7MGRD_0805 (2012)-MFG]  (hidden comment: LQM21PN4R7MGRD)
L18  value 4.7μH  [FP-LQM21PN4R7MGRD_0805 (2012)-MFG]  (hidden comment: LQM21PN4R7MGRD)
L19  value 270nH  [FP-LQW18ANR27G80D_0603 (1608)-MFG]  (hidden comment: LQW18ANR27G80D)
L20  value 270nH  [FP-LQW18ANR27G80D_0603 (1608)-MFG]  (hidden comment: LQW18ANR27G80D)
NT1  Net-Tie  [Net-Tie_10mil]  (net tie, no BOM)
Q5  CSD25485F5  [YJK0003A]
Q6  CSD17585F5T  [YJK0003A]
Q7  CSD17585F5T  [YJK0003A]
R60  ValueDisplayed: 200k  [0402]  (hidden comment: ERJ-2RKF2003X)
R61  ValueDisplayed: 1.00k  [0805_HV]  (hidden comment: RP73PF2A1K0BTDF)
R62  ValueDisplayed: 200k  [0402]  (hidden comment: ERJ-2RKF2003X)
R63  ValueDisplayed: 200k  [0402]  (hidden comment: ERJ-2RKF2003X)
R64  ValueDisplayed: 54.9k  [0402]  (hidden comment: CRCW040254K9FKED)
R65  ValueDisplayed: 63.4k  [0402]  (hidden comment: CRCW040263K4FKED)
R66  ValueDisplayed: 1.00k  [0402]  (hidden comment: RC0402FR-071KL)
R67  value 0  [FP-CRG0402ZR_0402-IPC_C]  (hidden comment: CRG0402ZR)
R68  ValueDisplayed: 2.74k  [0402]  (hidden comment: CRCW04022K74FKED)
R69  ValueDisplayed: 1.30k  [0402]  (hidden comment: CRCW04021K30FKED)
R70  ValueDisplayed: 10.0k  [0402]  (hidden comment: ERJ-2RKF1002X)
R71  ValueDisplayed: 10.0k  [0402]  (hidden comment: ERJ-2RKF1002X)
R72  ValueDisplayed: 10.0k  [0402]  (hidden comment: ERJ-2RKF1002X)
SW1  JS202011JCQN  [FP-JS202011JCQN-MFG]
T1  PWB3010LC  [FP-PWB3010LC_SMD6-MFG]
T2  ZA9756-AED  [FP-ZA9756-AED_SMD8-MFG]
TP19  TP_SM_1MM  [TP_SM_1MM]  (value not drawn)  (no BOM)
TP20  TP_SM_1MM  [TP_SM_1MM]  (value not drawn)  (no BOM)
TP21  TP_SM_1MM  [TP_SM_1MM]  (value not drawn)  (no BOM)
TP22  TP_SM_1MM  [TP_SM_1MM]  (value not drawn)  (no BOM)
U10  TLV1805DBVR  [DBV0006A_N]

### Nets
3.3V: R60.2 R64.2 R66.2 SW1.5
+12Va: C90.2 R70.1 U10.6(V+)
-12Va: C92.2 U10.2(V-) U10.5(SD)
GND: C90.1 C91.2 C92.1 C93.1 D14.1(1_IO) D15.2(GND) D16.2(GND) NT1.1 Q6.2(S) Q7.2(S) R62.1 R65.1 R68.1 R71.2 R72.2
AM62L_GPIO_EV_PlugIN: SW1.7 ; off-sheet AM62L_GPIO_EV_PlugIN
CP_EV: D17.2(Anode) J5.3
CP_N: C97.1 J4.2 NT1.2
CP_P: C107.1 D14.2(2_IO) J4.3 J5.2 R63.2
MSP_ADC_CP: C93.2 D15.1(I/O) R63.1 R64.1 R65.2 TP21.1 ; off-sheet MSP_ADC_CP
MSP_ADC_PP: R67.2 TP22.1 ; off-sheet MSP_ADC_PP
MSP_GPIO_EV_Charge: Q6.1(G) R71.1 ; off-sheet MSP_GPIO_EV_Charge
MSP_PWM_CP: TP20.1 U10.4(IN+) ; off-sheet MSP_PWM_CP
PLC_N: C101.2 C102.2 L15.1
PLC_P: C101.1 C102.1 L19.1
PP: D16.1(I/O) J4.1 J6.2 R67.1
NetC91_1: C91.1 J5.1 R61.2 TP19.1
NetC94_1: C94.1 C95.1 C98.2 C99.1 L17.2
NetC94_2: C94.2 C98.1 C105.2 C106.2 L16.2
NetC95_2: C95.2 C96.1 C99.2 C100.1 L18.2
NetC96_2: C96.2 C100.2 T1.1 T2.2
NetC97_2: C97.2 T1.6 T2.7
NetC103_1: C103.1 C104.1 L19.2 L20.1
NetC103_2: C103.2 C104.2 L15.2 L16.1
NetC105_1: C105.1 C106.1 C108.1 C111.2 L20.2
NetC107_2: C107.2 T1.4 T2.6
NetC108_2: C108.2 C109.1 C111.1 C112.1 L17.1
NetC109_2: C109.2 C110.1 C112.2 C113.1 L18.1
NetC110_2: C110.2 C113.2 T1.3 T2.3
NetD17_1: D17.1(Cathode) Q5.2(S)
NetJ6_1: J6.1 R66.1
NetQ5_1: Q5.1(G) Q7.3(D) R70.2
NetQ5_3: Q5.3(D) R68.2 R69.2
NetQ6_3: Q6.3(D) R69.1
NetQ7_1: Q7.1(G) R72.1 SW1.6(2_C)
NetR60_1: R60.1 R62.2 U10.3(IN-)
NetR61_1: R61.1 U10.1(OUT)

Not connected (* = marked no-connect by the designer): SW1 1* 2(1_C)* 3*; T1 2* 5*; T2 1(NC)* 4(NC)* 5(NC)* 8(NC)*

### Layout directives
differential pair: CP_N, CP_P, PLC_N, PLC_P

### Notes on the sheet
- Control Pilot
- (near J4) PP
- (near J4) CP
- (near J4) PE
- Proximity Detection
- PLC Impedance Matching Network
- (near J6) Jumper:
  ON = IEC-61851
  OFF = J1773
- EV - Simulation

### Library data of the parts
C90 C92 = CMP-0860555-1: as C56-C60 on sheet PROC219_PLC
C91 = CMP-0006453-2: CAP, CERM, 300 pF, 50 V, +/- 5%, C0G/NP0, 0402; Manufacturer: MuRata; TaMin_C: -55°C; Polarized: N; SizeAreaWB_mm2: 3; Value1: Unknown; U/M: EA; Value: 300pF; TaMax_C: 125°C; SizeZ_mm: 0.6; SizeX_mm: 1; SizeY_mm: 0.5; Value2: 50V; AEC Category: Q200
C93 C104 = CMP-0006196-2: CAP, CERM, 100 pF, 50 V, +/- 1%, C0G/NP0, 0402; Manufacturer: AVX; TaMin_C: -55°C; Polarized: N; SizeAreaWB_mm2: 3; Value1: Unknown; U/M: EA; Value: 100pF; TaMax_C: 125°C; SizeZ_mm: 0.6; SizeX_mm: 1; SizeY_mm: 0.5; Value2: 50V; AEC Category: Q200
C94 C111 = CMP-0006275-2: CAP, CERM, 2.2 uF, 16 V, +/- 10%, X5R, 0402; Manufacturer: TDK; TaMin_C: -55°C; Polarized: N; SizeAreaWB_mm2: 3; Value1: Unknown; U/M: EA; Value: 2.2uF; TaMax_C: 85°C; SizeZ_mm: 0.6; SizeX_mm: 1; SizeY_mm: 0.5; Value2: 16V; Cap_F: 2.2µF; AEC Category: Q200
C95 C112 = CMP-0104158-1: WCAP-CSGP Multilayer Ceramic Chip Capacitor, General Purpose, size 0402, NP0, 68pF, 50VDC; Manufacturer: Wurth Elektronik; Capacitance Tolerance: +/-5%; Insulation Resistance: 10GOhm; Q Factor: 1000; Rated Voltage (DC): 50V; Technical Reference: NP00402680J050DFCT10000
C96 C113 = CMP-0053498-1: WCAP-CSGP Multilayer Ceramic Chip Capacitor, General Purpose, size 0402, X7R, 680pF, 50VDC; Manufacturer: Wurth Elektronik; Capacitance Tolerance: +/-10%; Dissipation Factor: 2.5%; Insulation Resistance: 10GOhm; Rated Voltage (DC): 50V; Technical Reference: X7R0402681K050DFCT10000
C97 C107 = CMP-0860564-1: CAP, CERM, 2700 pF, 50 V,+/- 10%, X7R, 0402; Manufacturer: Samsung Electro-Mechanics; SizeX_mm: 1; Value2: 50V; U/M: EA; AEC Category: Q200; TaMax_C: 125°C; SizeAreaWB_mm2: 3; Value: 2700pF; SizeArea_mm2: 0.5; TaMin_C: -55°C; Cap_F: 2.7nF; AEC Qualified: N; SizeZ_mm: 0.6
C98 C108 = CMP-0006300-2: CAP, CERM, 1 uF, 10 V, +/- 10%, X7S, 0402; Manufacturer: TDK; TaMin_C: -55°C; ESR_ohm: 0.011416; Polarized: N; SizeAreaWB_mm2: 3; Value1: 0.011416 ohm; U/M: EA; Value: 1uF; TaMax_C: 125°C; SizeZ_mm: 0.6; SizeX_mm: 1; SizeY_mm: 0.5; Value2: 10V; Cap_F: 1µF; IRMS_A: 1.483A; AEC Category: Q200
C99 C109 = CMP-0053546-1: WCAP-CSGP Multilayer Ceramic Chip Capacitor, General Purpose, size 0402, X7R, 1.5nF, 50VDC; Manufacturer: Wurth Elektronik; Capacitance Tolerance: +/-10%; Dissipation Factor: 2.5%; Insulation Resistance: 10GOhm; Rated Voltage (DC): 50V; Technical Reference: X7R0402152K050DFCT10000
C100 C110 = CMP-0053550-1: WCAP-CSGP Multilayer Ceramic Chip Capacitor, General Purpose, size 0402, X7R, 2.2nF, 50VDC; Manufacturer: Wurth Elektronik; Capacitance Tolerance: +/-10%; Dissipation Factor: 2.5%; Insulation Resistance: 10GOhm; Rated Voltage (DC): 50V; Technical Reference: X7R0402222K050DFCT10000
C101 C102 = CMP-0104156-1: WCAP-CSGP Multilayer Ceramic Chip Capacitor, General Purpose, size 0402, NP0, 33pF, 50VDC; Manufacturer: Wurth Elektronik; Capacitance Tolerance: +/-5%; Insulation Resistance: 10GOhm; Q Factor: 1000; Rated Voltage (DC): 50V; Technical Reference: NP00402330J050DFCT10000
C103 = CMP-0112442-1: WCAP-CSRF Multilayer Ceramic Chip Capacitor, High Frequency, size 0402, NP0 Class I, 22pF, 50VDC; Manufacturer: Wurth Elektronik; Capacitance Tolerance: +/-5%; Insulation Resistance: 10GOhm; Q Factor: 840; Rated Voltage (DC): 50V; Technical Reference: NP00402220J050DFCT1R000
C105 = CMP-0065518-1: WCAP-CSRF Multilayer Ceramic Chip Capacitor, High Frequency, size 0402, NP0 Class I, 27pF, 50VDC; Manufacturer: Wurth Elektronik; Capacitance Tolerance: +/-5%; Insulation Resistance: 10GOhm; Q Factor: 940; Rated Voltage (DC): 50V; Technical Reference: NP00402270J050DFCT1R000
C106 = CMP-0114900-1: WCAP-CSGP Multilayer Ceramic Chip Capacitor, General Purpose, size 0402, NP0, 47pF, 50VDC; Manufacturer: Wurth Elektronik; Capacitance Tolerance: +/-5%; Insulation Resistance: 10GOhm; Q Factor: 1000; Rated Voltage (DC): 50V; Technical Reference: NP00402470J050DFCT10000
D14 = CMP-0124220-1: Bidirectional TVS Diodes in SOD-323 Package; Manufacturer: Texas Instruments; AEC Qualified: No; SizeZ_mm: 1mm; VRWM: 12V; Ipp: 15A; Ppk: 390W; Breakdown Voltage: 13.2V; Cap_F: 6.5pF; Clamping Voltage: 26V; Number Of Channels: 1; Standoff Height: 0mm; TaMax_C: +150°C; TaMin_C: -55°C
D15 D16 = CMP-0122929-1: One-channel unidirectional device for 3.3V surge protection in SOD-323 package; Manufacturer: Texas Instruments; SizeZ_mm: 1mm; AEC Qualified: No; Breakdown Voltage: 4.5V; Cap_F: 4.5pF; Clamping Voltage: 6.3V; Ipp: 25A; Number Of Channels: 1; Ppk: 170W; Standoff Height: 0mm; TaMax_C: +125°C; TaMin_C: -40°C; VRWM: 3.6V
D17 = CMP-0126831-1: RF Diode PIN - Single 30V 100 mA EMD2; Manufacturer: Rohm; AEC Qualified: No; SizeZ_mm: 0.7mm; TJmax_C: 150°C; Cap_F: 0.35pF; Forward Current: 100mA; Peak Reverse Current: 0.1uA
J4 = CMP-0124724-1: 3 Position Wire to Board Terminal Block Horizontal with Board 0.138" (3.50mm) Through Hole; Manufacturer: Wurth; ContactFinish: Tin,Nickel; Current_A: 10A; Row_Count: 1; Voltage_V: 300V; AEC Qualified: No; Conn Gender: Female; DUT-Pitch_mm: 3.5mm; Is Female: yes; Max Wire Gauge: 16; Min Wire Gauge: 30; SizeZ_mm: 9.2mm
J5 = CMP-0054796-4: as J3 on sheet PROC219_PLC
J6 = CMP-0054794-2: Header, 2.54 mm, 2x1, Gold, TH; Manufacturer: Wurth Elektronik; Shrouded: N; Gender: Male; Green_REACh: Passed; Pitch_mm: 2.54; Green_Lifecycle: Active; Row_Count: 1; Cert_UL: Y
L15 L16 L19 L20 = CMP-0124834-1: Wire Wound RF Inductor 270nH ±2% 260mA 2.42Ω 0603 (1608); Manufacturer: Murata; AEC Qualified: No; DCR_ohm: 2.42; Material: Non-Magnetic; SizeZ_mm: 1mm; Q Factor: 24; Self Resonant Frequency: 1.25GHz; Test Frequency: 100MHz
L17 L18 = CMP-0124833-1: Multilayer Type Inductor for Power Lines, 0805 (2012), 4.7μH, 20%, 0.288Ω, 0.8A; Manufacturer: Murata; AEC Qualified: No; DCR_ohm: 0.288; Material: Ferrite; SizeZ_mm: 1mm; Self Resonant Frequency: 30MHz; Shrouded: true; Test Frequency: 1MHz
NT1 = CMP-0078142-6: Single point connection between nets.
Q5 = CMP-0000031-3: MOSFET, P-CH, -20 V, -5.3 A, YJK0003A (PICOSTAR-3); Manufacturer: Texas Instruments; Alternate Manufacturer: None; SizeZ_mm: 0.35; SizeX_mm: 1.49; ChType: P; Vgs_V: -12V; Value2: 2.7 nC; SizeArea_mm2: 1.0877; QgTyp_nC: 2.7; SizeY_mm: 0.73; AEC Category: Q101; IdsMax_A: -5.3A; AEC Qualified: N; Value: -20V; SizeAreaWB_mm2: 4.3077; ChMode: Enhancement
Q6 Q7 = CMP-0067551-1: MOSFET, N-CH, 30 V, 5.9 A, YJK0003A (PICOSTAR-3); Alternate Manufacturer: None; Manufacturer: Texas Instruments; Rdson45_ohm: 0.033; QgTyp_nC: 1.9; SizeAreaWB_mm2: 4.3077; Vgs_V: 20V; Value1: 0.033 ohm; VdsMax_V: 30V; U/M: EA; Value: 30V; IdsMax_A: 5.9A; SizeZ_mm: 0.35; SizeX_mm: 1.49; SizeY_mm: 0.73; Value2: 1.9 nC; SizeArea_mm2: 1.0877; ChType: N; AEC Category: Q101
R60 R62 R63 = CMP-0026677-1: RES, 200 k, 1%, 0.1 W, 0402; Manufacturer: Panasonic; Power_W: 100mW; TempCo: 100 ppm/C; U/M: EA; Value: 200k; EIA_Code: E96; SizeX_mm: 1; SizeY_mm: 0.5; SizeZ_mm: 0.6; Value2: 0.1W; VDC_V: 50V; AEC Category: Q200
R61 = CMP-0019089-2: RES, 1.00 k, 0.1%, 0.25 W, 0805; Manufacturer: TE Connectivity; Power_W: 250mW; TempCo: 25 ppm/C; Value_Code: 1k00; U/M: EA; Value: 1.00k; EIA_Code: E192; Res_ohm: 1k; SizeX_mm: 2; SizeY_mm: 1.25; SizeZ_mm: 1.45; Value2: 0.25W; SizeArea_mm2: 2.5; VDC_V: 150V; AEC Category: Q200
R64 = CMP-0026449-2: RES, 54.9 k, 1%, 0.063 W, AEC-Q200 Grade 0, 0402; Manufacturer: Vishay-Dale; Power_W: 63mW; TempCo: 100 ppm/C; Value_Code: 54k9; Value: 54.9k; EIA_Code: E96; SizeX_mm: 1; SizeY_mm: 0.5; SizeZ_mm: 0.6; Value2: 0.063W; AEC Qualified: Y; VDC_V: 50V; AEC Category: Q200; AEC Grade: 0
R65 = CMP-0026494-2: RES, 63.4 k, 1%, 0.063 W, AEC-Q200 Grade 0, 0402; Manufacturer: Vishay-Dale; Power_W: 63mW; TempCo: 100 ppm/C; Value_Code: 63k4; Value: 63.4k; EIA_Code: E96; SizeX_mm: 1; SizeY_mm: 0.5; SizeZ_mm: 0.6; Value2: 0.063W; AEC Qualified: Y; VDC_V: 50V; AEC Category: Q200; AEC Grade: 0
R66 = CMP-0026725-1: RES, 1.00 k, 1%, 0.0625 W, 0402; Manufacturer: Yageo America; Power_W: 62.5mW; TempCo: 100 ppm/C; Value_Code: 1k00; U/M: EA; Value: 1.00k; EIA_Code: E96; Res_ohm: 1k; SizeX_mm: 1; SizeY_mm: 0.5; SizeZ_mm: 0.6; AEC Qualified: N; VDC_V: 50V; AEC Category: Q200
R67 = CMP-0095664-1: as R51-R56 on sheet PROC219_PLC
R68 = CMP-0026241-2: RES, 2.74 k, 1%, 0.063 W, AEC-Q200 Grade 0, 0402; Manufacturer: Vishay-Dale; Power_W: 63mW; TempCo: 100 ppm/C; Value_Code: 2k74; Value: 2.74k; EIA_Code: E96; SizeX_mm: 1; SizeY_mm: 0.5; SizeZ_mm: 0.6; Value2: 0.063W; AEC Qualified: Y; VDC_V: 50V; AEC Category: Q200; AEC Grade: 0
R69 = CMP-0026082-3: RES, 1.30 k, 1%, 0.063 W, AEC-Q200 Grade 0, 0402; Manufacturer: Vishay-Dale; Power_W: 63mW; TempCo: 100 ppm/C; Value_Code: 1k30; Value: 1.30k; EIA_Code: E96; Res_ohm: 1.3k; SizeX_mm: 1; SizeY_mm: 0.5; SizeZ_mm: 0.6; Value2: 0.063W; AEC Qualified: Y; VDC_V: 50V; AEC Category: Q200; AEC Grade: 0
R70-R72 = CMP-0026658-1: RES, 10.0 k, 1%, 0.1 W, 0402; Manufacturer: Panasonic; Power_W: 100mW; TempCo: 100 ppm/C; Value_Code: 10k0; U/M: EA; Value: 10.0k; EIA_Code: E96; Res_ohm: 10k; SizeX_mm: 1; SizeY_mm: 0.5; SizeZ_mm: 0.6; Value2: 0.1W; VDC_V: 50V; AEC Category: Q200
SW1 = CMP-10038-000009-1: SWITCH SLIDE DPDT 300MA 6V; Manufacturer: C&K; Actuator Material: Nylon; Actuator Length: 2mm; Actuator Type: Standard; Electrical Life: 5000Cycles; Switch Function: On-On
T1 = CMP-0124838-1: Wideband RF transformer, 1:1, 0.0035-125 MHz, SMT, RoHS; Manufacturer: Coilcraft; DCR_ohm: 0.32; Ind_H: 780µH; SizeZ_mm: 4.65mm; AEC Qualified: No; Frequency_Fixed: 125MHz; Insertion Loss: 0.2dB; TaMax_C: +85°C; TaMin_C: -40°C; Voltage_Isolation_Vrms: 300Vrms
T2 = CMP-0124847-1: 215µH Isolation and Data Interface (Encapsulated) Pulse Transformer 1:1 Surface Mount; Manufacturer: Coilcraft; DCR_ohm: 0.22; Rsec1_ohm: 0.26; SizeZ_mm: 6mm; AEC Qualified: Yes; AEC Grade: Grade 1; TaMax_C: +125°C; TaMin_C: -40°C; Voltage_Isolation_Vrms: 3000Vrms
TP19-TP22 = CMP-0003825-1: 1mm Test Point, SMT; Manufacturer: Any
U10 = CMP-0080757-2: 40 V, microPower, Push-Pull Comparator with Shutdown, DBV0006A (SOT-23-6); Alternate Manufacturer: Texas Instruments; SizeAreaWB_mm2: 14.82; SizeZ_mm: 1.45; SizeX_mm: 2.8; SizeY_mm: 2.9; SizeArea_mm2: 8.12; CompType: IC; AEC Qualified: N; AEC Category: Q200

## Sheet PROC219_GBT.SchDoc
size 431 x 279 mm; Date: Not shown in title block; ApprovedBy: Not shown in title block; CheckedBy: Not shown in title block; Author: Not shown in title block; CompanyName: Not shown in title block; Engineer: Not shown in title block; Organization: Not shown in title block; Address1: Not shown in title block; Address2: Not shown in title block; Address3: Not shown in title block; Address4: Not shown in title block; DocumentNumber: 1; Revision: Use project parameter SCH_Rev; SheetNumber: 7; SheetTotal: 16; PageSetup: Record=PageOptions¦CenterHorizontal=True¦CenterVertical=True¦PrintScale=1.00¦XCorrection=1.00¦YCorrection=1.00¦PrintKind=0¦BorderSize=5000000¦LeftOffset=0¦BottomOffset=0¦Orientation=2¦PaperLength=1000¦PaperWidth=1000¦Scale=100¦PaperSource=15¦PrintQuality=600¦MediaType=1¦DitherType=10¦PaperKind=Letter¦PrintScaleMode=1
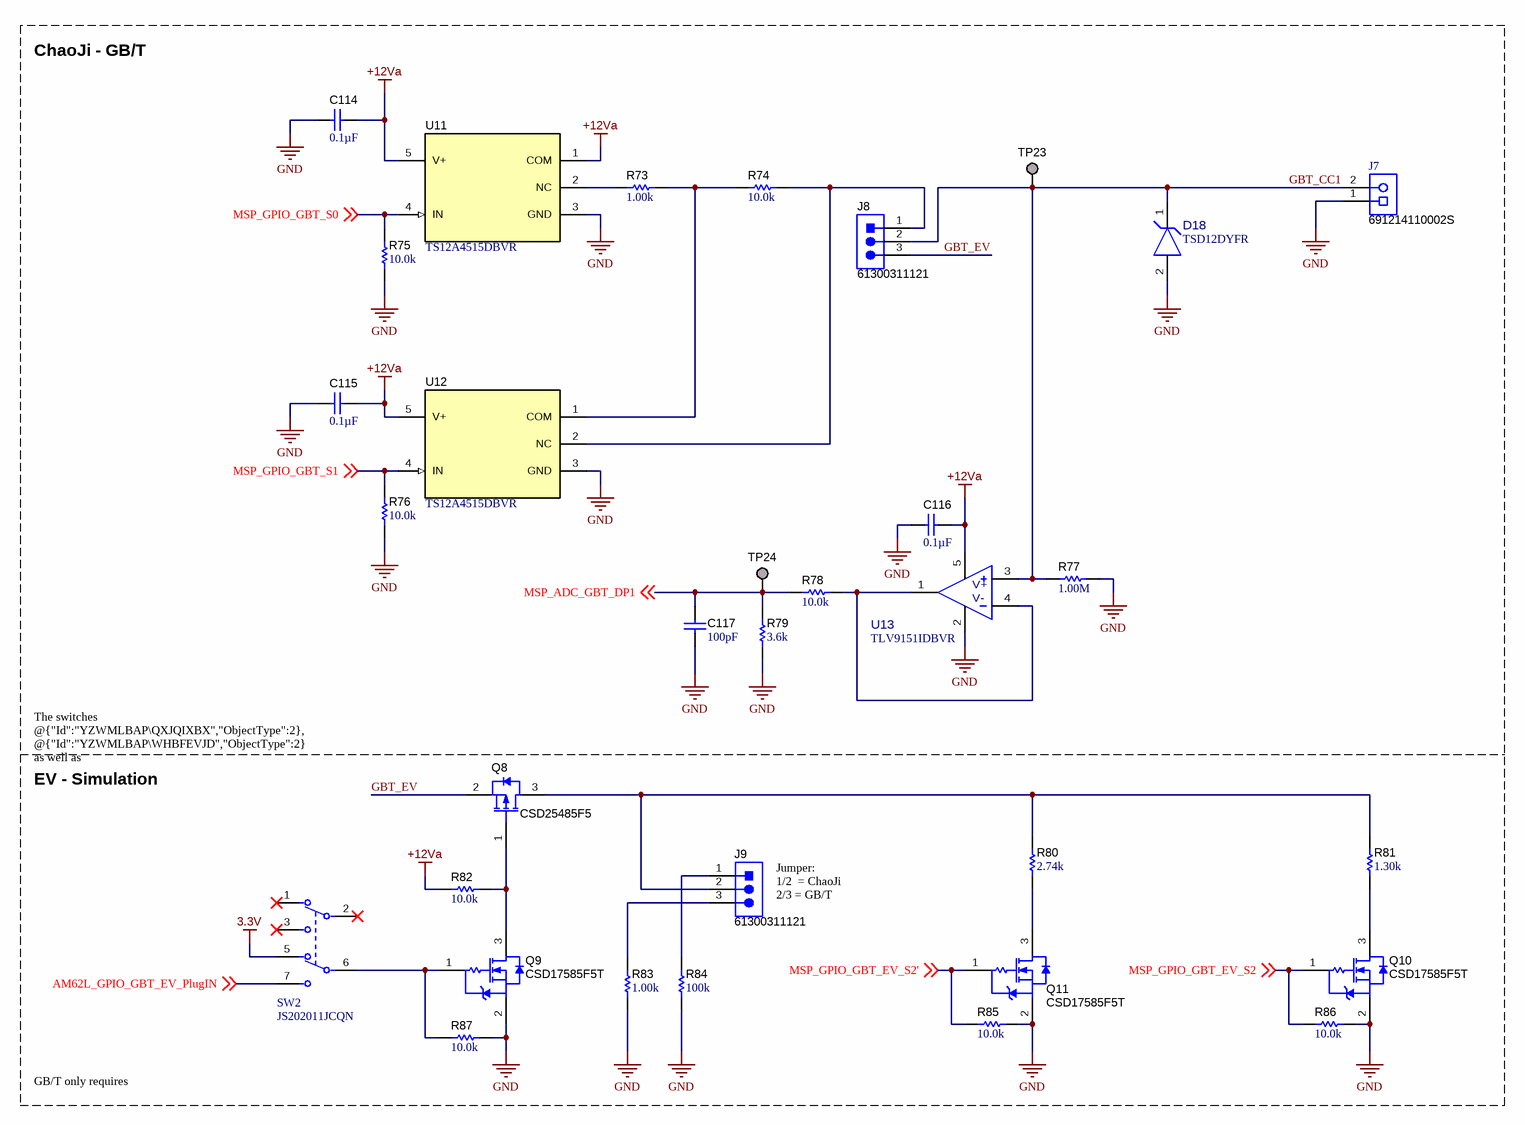
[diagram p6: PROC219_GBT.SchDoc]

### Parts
C114  ValueDisplayed: 0.1µF  [0402]  (hidden comment: CC0402KRX7R8BB104)
C115  ValueDisplayed: 0.1µF  [0402]  (hidden comment: CC0402KRX7R8BB104)
C116  ValueDisplayed: 0.1µF  [0402]  (hidden comment: CC0402KRX7R8BB104)
C117  ValueDisplayed: 100pF  [0402]  (hidden comment: 04025A101FAT2A)
D18  TSD12DYFR  [DYF0002A-MFG]
J7  691214110002S  [FP-691214110002S_HDR2-MFG]
J8  61300311121  [WURTH_61300311121]
J9  61300311121  [WURTH_61300311121]
Q8  CSD25485F5  [YJK0003A]
Q9  CSD17585F5T  [YJK0003A]
Q10  CSD17585F5T  [YJK0003A]
Q11  CSD17585F5T  [YJK0003A]
R73  ValueDisplayed: 1.00k  [1206]  (hidden comment: RP73D2B1K0BTG)
R74  ValueDisplayed: 10.0k  [0805_HV]  (hidden comment: RT0805BRD0710KL)
R75  ValueDisplayed: 10.0k  [0402]  (hidden comment: ERJ-2RKF1002X)
R76  ValueDisplayed: 10.0k  [0402]  (hidden comment: ERJ-2RKF1002X)
R77  ValueDisplayed: 1.00M  [0402]  (hidden comment: RC0402FR-071ML)
R78  ValueDisplayed: 10.0k  [0402]  (hidden comment: ERJ-2RKF1002X)
R79  ValueDisplayed: 3.6k  [0402]  (hidden comment: CRCW04023K60JNED)
R80  ValueDisplayed: 2.74k  [0603]  (hidden comment: RT0603BRD072K74L)
R81  ValueDisplayed: 1.30k  [0603]  (hidden comment: RT0603BRD071K3L)
R82  ValueDisplayed: 10.0k  [0402]  (hidden comment: ERJ-2RKF1002X)
R83  ValueDisplayed: 1.00k  [0402]  (hidden comment: RC0402FR-071KL)
R84  ValueDisplayed: 100k  [0402]  (hidden comment: RC0402FR-07100KL)
R85  ValueDisplayed: 10.0k  [0402]  (hidden comment: ERJ-2RKF1002X)
R86  ValueDisplayed: 10.0k  [0402]  (hidden comment: ERJ-2RKF1002X)
R87  ValueDisplayed: 10.0k  [0402]  (hidden comment: ERJ-2RKF1002X)
SW2  JS202011JCQN  [FP-JS202011JCQN-MFG]
TP23  TP_SM_1MM  [TP_SM_1MM]  (value not drawn)  (no BOM)
TP24  TP_SM_1MM  [TP_SM_1MM]  (value not drawn)  (no BOM)
U11  TS12A4515DBVR  [DBV0005A_N]
U12  TS12A4515DBVR  [DBV0005A_N]
U13  TLV9151IDBVR  [DBV0005A-MFG]

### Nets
3.3V: SW2.5
+12Va: C114.2 C115.2 C116.1 R82.1 U11.1(COM) U11.5(V+) U12.5(V+) U13.5(V+)
GND: C114.1 C115.1 C116.2 C117.1 D18.2(GND) J7.1 Q9.2(S) Q10.2(S) Q11.2(S) R75.1 R76.1 R77.2 R79.1 R83.1 R84.1 R85.2 R86.2 R87.2 U11.3(GND) U12.3(GND) U13.2(V-)
AM62L_GPIO_GBT_EV_PlugIN: SW2.7 ; off-sheet AM62L_GPIO_GBT_EV_PlugIN
GBT_CC1: D18.1(IO) J7.2 J8.2 R77.1 TP23.1 U13.3(IN+)
GBT_EV: J8.3 Q8.2(S)
MSP_ADC_GBT_DP1: C117.2 R78.1 R79.2 TP24.1 ; off-sheet MSP_ADC_GBT_DP1
MSP_GPIO_GBT_EV_S2: Q10.1(G) R86.1 ; off-sheet MSP_GPIO_GBT_EV_S2
MSP_GPIO_GBT_EV_S2': Q11.1(G) R85.1 ; off-sheet MSP_GPIO_GBT_EV_S2'
MSP_GPIO_GBT_S0: R75.2 U11.4(IN) ; off-sheet MSP_GPIO_GBT_S0
MSP_GPIO_GBT_S1: R76.2 U12.4(IN) ; off-sheet MSP_GPIO_GBT_S1
NetJ8_1: J8.1 R74.2 U12.2(NC)
NetJ9_1: J9.1 R84.2
NetJ9_2: J9.2 Q8.3(D) R80.2 R81.2
NetJ9_3: J9.3 R83.2
NetQ8_1: Q8.1(G) Q9.3(D) R82.2
NetQ9_1: Q9.1(G) R87.1 SW2.6(2_C)
NetQ10_3: Q10.3(D) R81.1
NetQ11_3: Q11.3(D) R80.1
NetR73_1: R73.1 U11.2(NC)
NetR73_2: R73.2 R74.1 U12.1(COM)
NetR78_2: R78.2 U13.1(OUT) U13.4(IN-)

Not connected (* = marked no-connect by the designer): SW2 1* 2(1_C)* 3*

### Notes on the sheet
- ChaoJi - GB/T
- EV - Simulation
- The switches @{"Id":"YZWMLBAP\QXJQIXBX","ObjectType":2}, @{"Id":"YZWMLBAP\WHBFEVJD","ObjectType":2} as well as @{"Id":"YZWMLBAP\ATOUKVIF","ObjectType":2}, @{"Id":"YZWMLBAP\DYFQBADK","ObjectType":2} are only required for ChaoJi. For GB/T, both switches shall be closed.
- (near J9) Jumper:
  1/2  = ChaoJi
  2/3 = GB/T
- GB/T only requires @{"Id":"YZWMLBAP\ZQDAUZXW","ObjectType":2} for simulation.

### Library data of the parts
C114-C116 = CMP-0860555-1: as C56-C60 on sheet PROC219_PLC
C117 = CMP-0006196-2: as C93 on sheet PROC219_Pilot_Interface
D18 = CMP-0125981-1: 23V Clamp 18A (8/20µs) Ipp Tvs Diode Surface Mount SOD-323; Manufacturer: Texas Instruments; AEC Qualified: No; SizeZ_mm: 1mm; VRWM: 12V; Ppk: 300W; Breakdown Voltage: 12.7V; Cap_F: 12pF; Direction: Unidirectional; Number Of Channels: 1; Standoff Height: 0mm; TaMax_C: +150°C; TaMin_C: -55°C
J7 = CMP-0093089-2: 2 Position Wire to Board Terminal Block Horizontal with Board 0.138" (3.50mm) Through Hole; Manufacturer: Wurth; ContactFinish: Tin,Nickel; AEC Qualified: No; Max Wire Gauge: 16; Voltage_V: 300V; SizeZ_mm: 9.2mm; Current_A: 10A; DUT-Pitch_mm: 3.5mm; Min Wire Gauge: 30; Conn Gender: Female; Row_Count: 1; Is Female: yes
J8 J9 = CMP-0054796-4: as J3 on sheet PROC219_PLC
Q8 = CMP-0000031-3: as Q5 on sheet PROC219_Pilot_Interface
Q9-Q11 = CMP-0067551-1: as Q6 on sheet PROC219_Pilot_Interface
R73 = CMP-0018797-2: RES, 1.00 k, 0.1%, 0.25 W, 1206; Manufacturer: TE Connectivity; Power_W: 250mW; TempCo: 15 ppm/C; Value_Code: 1k00; U/M: EA; Value: 1.00k; EIA_Code: E192; Res_ohm: 1k; SizeX_mm: 3.2; SizeY_mm: 1.6; SizeZ_mm: 1.35; Value2: 0.25W; SizeArea_mm2: 5.12; AEC Qualified: N; VDC_V: 200V; AEC Category: Q200
R74 = CMP-0019464-2: RES, 10.0 k, 0.1%, 0.125 W, 0805; Manufacturer: Yageo America; Power_W: 125mW; TempCo: 25 ppm/C; Value_Code: 10k0; U/M: EA; Value: 10.0k; EIA_Code: E192; Res_ohm: 10k; SizeX_mm: 2; SizeY_mm: 1.25; SizeZ_mm: 1.45; Value2: 0.125W; SizeArea_mm2: 2.5; VDC_V: 150V; AEC Category: Q200
R75 R76 R78 R82 R85-R87 = CMP-0026658-1: as R70-R72 on sheet PROC219_Pilot_Interface
R77 = CMP-0026727-1: as R57 on sheet PROC219_PLC
R79 = CMP-0026919-5: RES, 3.6 k, 5%, 0.063 W, AEC-Q200 Grade 0, 0402; Manufacturer: Vishay-Dale; Power_W: 63mW; TempCo: 200 ppm/C; Value_Code: 3k60; Value: 3.6k; EIA_Code: E24; SizeX_mm: 1; SizeY_mm: 0.5; SizeZ_mm: 0.6; Value2: 0.063W; AEC Qualified: Y; VDC_V: 50V; AEC Category: Q200; AEC Grade: 0
R80 = CMP-0024081-3: RES, 2.74 k, 0.1%, 0.1 W, 0603; Manufacturer: Yageo America; Power_W: 100mW; TempCo: 25 ppm/C; Value_Code: 2k74; U/M: EA; Value: 2.74k; EIA_Code: E192; SizeX_mm: 1.6; SizeY_mm: 0.8; SizeZ_mm: 1; Value2: 0.1W; SizeArea_mm2: 1.28; VDC_V: 75V; AEC Category: Q200
R81 = CMP-0023888-3: RES, 1.30 k, 0.1%, 0.1 W, 0603; Manufacturer: Yageo America; Power_W: 100mW; TempCo: 25 ppm/C; Value_Code: 1k30; U/M: EA; EIA_Code: E192; Res_ohm: 1.3k; SizeX_mm: 1.6; SizeY_mm: 0.8; SizeZ_mm: 1; Value2: 0.1W; SizeArea_mm2: 1.28; VDC_V: 75V; AEC Category: Q200; Value: 1.30k
R83 = CMP-0026725-1: as R66 on sheet PROC219_Pilot_Interface
R84 = CMP-0026721-1: RES, 100 k, 1%, 0.0625 W, 0402; Manufacturer: Yageo America; Power_W: 62.5mW; TempCo: 100 ppm/C; U/M: EA; Value: 100k; EIA_Code: E96; SizeX_mm: 1; SizeY_mm: 0.5; SizeZ_mm: 0.6; AEC Qualified: N; VDC_V: 50V; AEC Category: Q200
SW2 = CMP-10038-000009-1: as SW1 on sheet PROC219_Pilot_Interface
TP23 TP24 = CMP-0003825-1: 1mm Test Point, SMT; Manufacturer: Any
U11 U12 = CMP-0067409-1: Low-Voltage, Low On-State Resistance SPST CMOS Analog Switches, DBV0005A (SOT-23-5); Alternate Manufacturer: Texas Instruments; SizeAreaWB_mm2: 14.82; U/M: EA; SizeZ_mm: 1.45; SizeX_mm: 2.8; SizeY_mm: 2.9; SizeArea_mm2: 8.12; CompType: IC
U13 = CMP-0092482-1: Single 4.5-MHz, 16-V rail-to-rail input/output, low-offset voltage, low-noise op amp 5-SOT-23 -40 to 125; Manufacturer: Texas Instruments; TJmax_C: +150°C; TaMax_C: +125°C; TaMin_C: -40°C; Voltage Gain: 120dB; Input Bias Current: 0.00001uA; Response Time: 2.5us; Max Dual Supply Voltage: 8V; Nominal Supply Current: 560uA; Number Of Channels: 1; SizeZ_mm: 1.45mm; Input Offset Voltage: 0.125mV; Max Supply Voltage: 16V; Min Supply Voltage: 2.7V; AEC Qualified: No; Output Current Per Channel: 75mA; Gain Bandwidth: 4.5MHz; Standoff Height: 0mm; Min Dual Supply Voltage: 1.35V

## Sheet PROC219_CHAdeMO.SchDoc
size 431 x 279 mm; Date: Not shown in title block; ApprovedBy: Not shown in title block; CheckedBy: Not shown in title block; Author: Not shown in title block; CompanyName: Not shown in title block; Engineer: Not shown in title block; Organization: Not shown in title block; Address1: Not shown in title block; Address2: Not shown in title block; Address3: Not shown in title block; Address4: Not shown in title block; DocumentNumber: 1; Revision: Use project parameter SCH_Rev; SheetNumber: 8; SheetTotal: 16; PageSetup: Record=PageOptions¦CenterHorizontal=True¦CenterVertical=True¦PrintScale=1.00¦XCorrection=1.00¦YCorrection=1.00¦PrintKind=0¦BorderSize=5000000¦LeftOffset=0¦BottomOffset=0¦Orientation=2¦PaperLength=1000¦PaperWidth=1000¦Scale=100¦PaperSource=15¦PrintQuality=600¦MediaType=1¦DitherType=10¦PaperKind=Letter¦PrintScaleMode=1
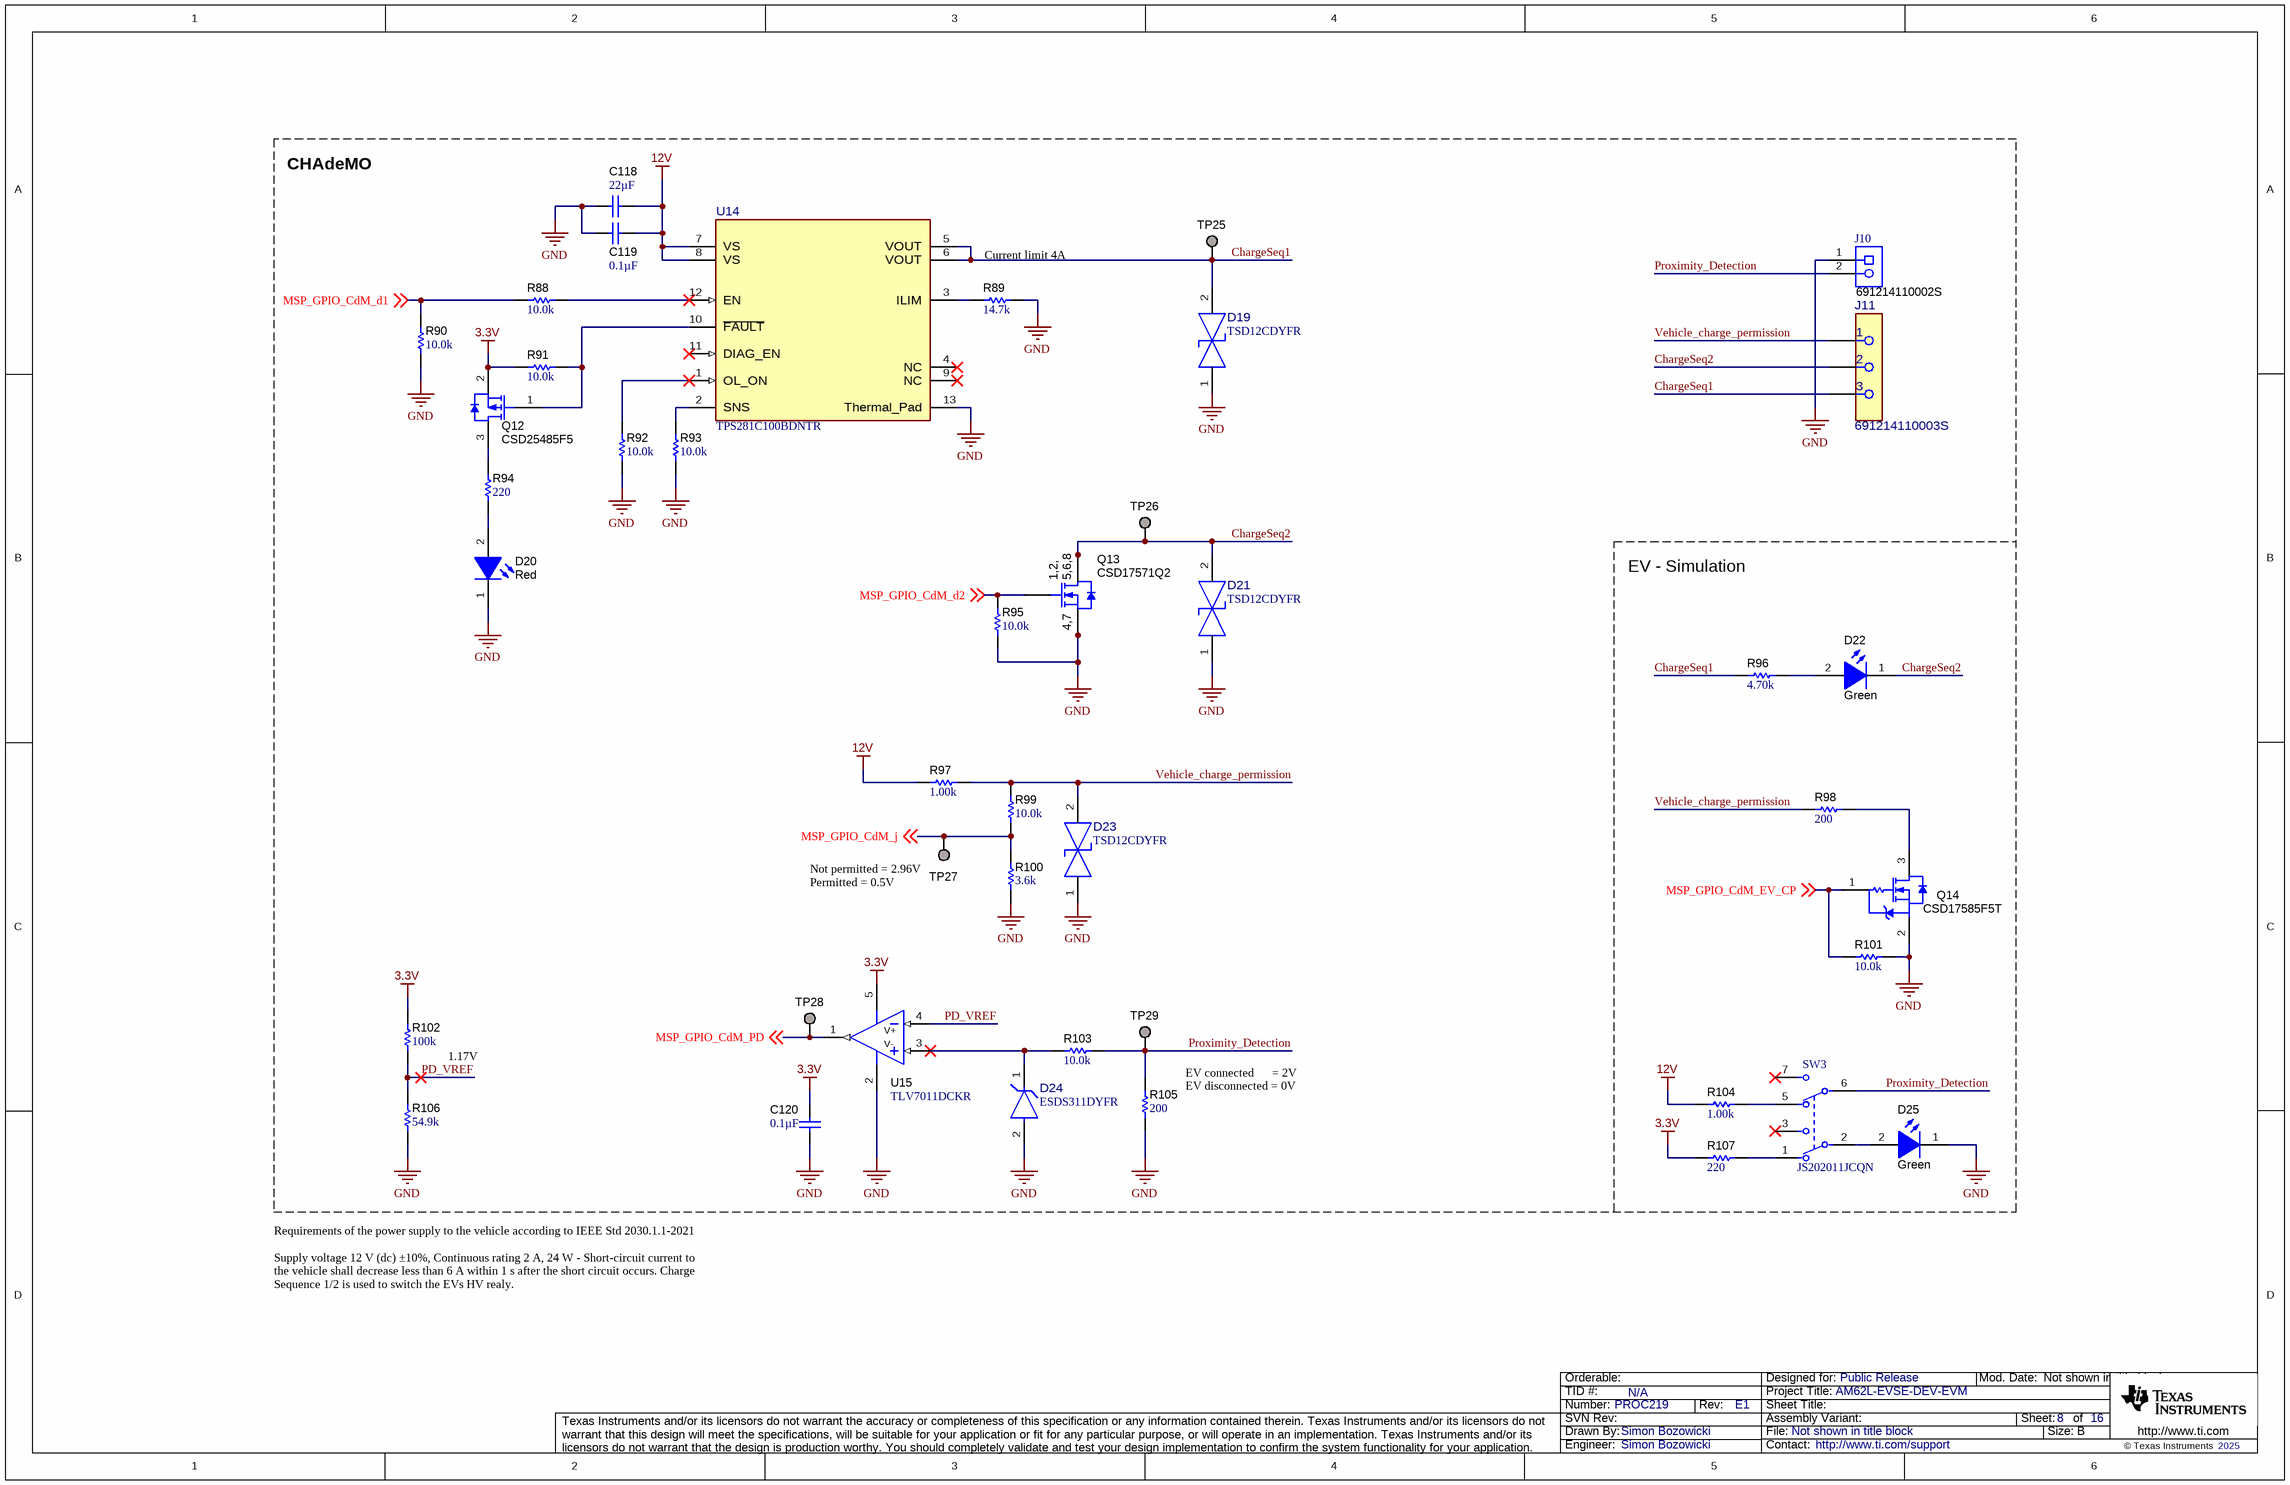
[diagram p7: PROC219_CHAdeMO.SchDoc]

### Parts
C118  ValueDisplayed: 22µF  [1210_270]  (hidden comment: CC1210KKX7R8BB226)
C119  ValueDisplayed: 0.1µF  [0402]  (hidden comment: CC0402KRX7R8BB104)
C120  ValueDisplayed: 0.1µF  [0402]  (hidden comment: CC0402KRX7R8BB104)
D19  TSD12CDYFR  [DYF0002A-CA-MFG]
D20  value Red  [WL-SMCW_RED]  (hidden comment: 150060RS75000)
D21  TSD12CDYFR  [DYF0002A-CA-MFG]
D22  value Green  [WL-SMCW_GREEN]  (hidden comment: 150060VS75000)
D23  TSD12CDYFR  [DYF0002A-CA-MFG]
D24  ESDS311DYFR  [DYF0002A-MFG]
D25  value Green  [WL-SMCW_GREEN]  (hidden comment: 150060VS75000)
J10  691214110002S  [FP-691214110002S_HDR2-MFG]
J11  691214110003S  [FP-691214110003S_CONN_TERM_BLK_3-MFG]
Q12  CSD25485F5  [YJK0003A]
Q13  CSD17571Q2  [DQK0006C]
Q14  CSD17585F5T  [YJK0003A]
R88  ValueDisplayed: 10.0k  [0402]  (hidden comment: ERJ-2RKF1002X)
R89  ValueDisplayed: 14.7k  [0402]  (hidden comment: CRCW040214K7FKED)
R90  ValueDisplayed: 10.0k  [0402]  (hidden comment: ERJ-2RKF1002X)
R91  ValueDisplayed: 10.0k  [0402]  (hidden comment: ERJ-2RKF1002X)
R92  ValueDisplayed: 10.0k  [0402]  (hidden comment: ERJ-2RKF1002X)
R93  ValueDisplayed: 10.0k  [0402]  (hidden comment: ERJ-2RKF1002X)
R94  ValueDisplayed: 220  [0402]  (hidden comment: CRCW0402220RJNED)
R95  ValueDisplayed: 10.0k  [0402]  (hidden comment: ERJ-2RKF1002X)
R96  ValueDisplayed: 4.70k  [0402]  (hidden comment: ERJ-2RKF4701X)
R97  ValueDisplayed: 1.00k  [1206]  (hidden comment: RP73D2B1K0BTG)
R98  ValueDisplayed: 200  [0805_HV]  (hidden comment: RT0805BRD07200RL)
R99  ValueDisplayed: 10.0k  [0402]  (hidden comment: ERJ-2RKF1002X)
R100  ValueDisplayed: 3.6k  [0402]  (hidden comment: CRCW04023K60JNED)
R101  ValueDisplayed: 10.0k  [0402]  (hidden comment: ERJ-2RKF1002X)
R102  ValueDisplayed: 100k  [0402]  (hidden comment: RC0402FR-07100KL)
R103  ValueDisplayed: 10.0k  [0402]  (hidden comment: ERJ-2RKF1002X)
R104  ValueDisplayed: 1.00k  [1206]  (hidden comment: RP73D2B1K0BTG)
R105  ValueDisplayed: 200  [0805_HV]  (hidden comment: RT0805BRD07200RL)
R106  ValueDisplayed: 54.9k  [0402]  (hidden comment: CRCW040254K9FKED)
R107  ValueDisplayed: 220  [0402]  (hidden comment: CRCW0402220RJNED)
SW3  JS202011JCQN  [FP-JS202011JCQN-MFG]
TP25  TP_SM_1MM  [TP_SM_1MM]  (value not drawn)  (no BOM)
TP26  TP_SM_1MM  [TP_SM_1MM]  (value not drawn)  (no BOM)
TP27  TP_SM_1MM  [TP_SM_1MM]  (value not drawn)  (no BOM)
TP28  TP_SM_1MM  [TP_SM_1MM]  (value not drawn)  (no BOM)
TP29  TP_SM_1MM  [TP_SM_1MM]  (value not drawn)  (no BOM)
U14  TPS281C100BDNTR  [DNT0012B-MFG]
U15  TLV7011DCKR  [DCK0005A_N]

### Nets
3.3V: C120.1 Q12.2(S) R91.1 R102.2 R107.2 U15.5(V+)
12V: C118.1 C119.2 R97.1 R104.1 U14.7(VS) U14.8(VS)
GND: C118.2 C119.1 C120.2 D19.1(1_IO) D20.1(K) D21.1(1_IO) D23.1(1_IO) D24.2(GND) D25.1(K) J10.1 Q13.4(S) Q13.7(S) Q14.2(S) R89.1 R90.2 R92.1 R93.1 R95.1 R100.1 R101.2 R105.1 R106.1 U14.13(Thermal_Pad) U15.2(V-)
ChargeSeq1: D19.2(2_IO) J11.3 R96.1 TP25.1 U14.5(VOUT) U14.6(VOUT)
ChargeSeq2: D21.2(2_IO) D22.1(K) J11.2 Q13.1(D) Q13.2(D) Q13.5(D) Q13.6(D) Q13.8(D) TP26.1
MSP_GPIO_CdM_d1: R88.1 R90.1 ; off-sheet MSP_GPIO_CdM_d1
MSP_GPIO_CdM_d2: Q13.3(G) R95.2 ; off-sheet MSP_GPIO_CdM_d2
MSP_GPIO_CdM_EV_CP: Q14.1(G) R101.1 ; off-sheet MSP_GPIO_CdM_EV_CP
MSP_GPIO_CdM_j: R99.2 R100.2 TP27.1 ; off-sheet MSP_GPIO_CdM_j
MSP_GPIO_CdM_PD: TP28.1 U15.1(OUT) ; off-sheet MSP_GPIO_CdM_PD
PD_VREF: R102.1 R106.2 U15.4(IN-)
Proximity_Detection: J10.2 R103.1 R105.2 SW3.6(2_C) TP29.1
Vehicle_charge_permission: D23.2(2_IO) J11.1 R97.2 R98.2 R99.1
NetD20_2: D20.2(A) R94.1
NetD22_2: D22.2(A) R96.2
NetD24_1: D24.1(I/O) R103.2 U15.3(IN+)
NetD25_2: D25.2(A) SW3.2(1_C)
NetQ12_1: Q12.1(G) R91.2 U14.10(~{FAULT})
NetQ12_3: Q12.3(D) R94.2
NetQ14_3: Q14.3(D) R98.1
NetR88_2: R88.2 U14.12(EN)
NetR89_2: R89.2 U14.3(ILIM)
NetR92_2: R92.2 U14.1(OL_ON)
NetR93_2: R93.2 U14.2(SNS)
NetR104_2: R104.2 SW3.5
NetR107_1: R107.1 SW3.1

Not connected (* = marked no-connect by the designer): SW3 3* 7*; U14 4(NC)* 9(NC)* 11(DIAG_EN)*

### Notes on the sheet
- CHAdeMO
- (near R89) Current limit 4A
- EV - Simulation
- (near TP27) Not permitted = 2.96V
  Permitted = 0.5V
- 1.17V
- EV connected      = 2V
  EV disconnected = 0V
- Requirements of the power supply to the vehicle according to IEEE Std 2030.1.1-2021
  Supply voltage 12 V (dc) ±10%, Continuous rating 2 A, 24 W - Short-circuit current to the vehicle shall decrease less than 6 A within 1 s after the short circuit occurs. Charge Sequence 1/2 is used to switch the EVs HV realy.

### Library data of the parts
C118 = CMP-0082267-1: CAP, CERM, 22 µF, 25 V,+/- 10%, X7R, 1210; Manufacturer: Yageo; TaMin_C: -55°C; ESR_ohm: 1m; Polarized: N; SizeAreaWB_mm2: 14.7; Value1: 0.001 ohm; U/M: EA; Value: 22uF; TaMax_C: 125°C; SizeZ_mm: 2.7; SizeX_mm: 3.2; SizeY_mm: 2.5; Cap_Case: 1210; Value2: 25V; SizeArea_mm2: 8; AEC Category: Q200
C119 C120 = CMP-0860555-1: as C56-C60 on sheet PROC219_PLC
D19 D21 D23 = CMP-0124220-1: as D14 on sheet PROC219_Pilot_Interface
D20 = CMP-0002947-3: LED, Red, SMD; Manufacturer: Wurth Elektronik; Value1: 0.072W; Vf_V: 2V; Angle: 140; Tjmax_C: 85°C; Type: AlInGaP; Vr_V: 5V; Io_A: 30mA; Power_TotalModule: 72mW
D22 D25 = CMP-0002894-2: LED, Green, SMD; Manufacturer: Wurth Elektronik; Type: AlInGaP; Value2: 2V; Io_A: 20mA; Value1: W
D24 = CMP-0122929-1: as D15 on sheet PROC219_Pilot_Interface
J10 = CMP-0093089-2: as J7 on sheet PROC219_GBT
J11 = CMP-0124724-1: as J4 on sheet PROC219_Pilot_Interface
Q12 = CMP-0000031-3: as Q5 on sheet PROC219_Pilot_Interface
Q13 = CMP-0000585-1: MOSFET, N-CH, 30 V, 22 A, DQK0006C (WSON-6); Alternate Manufacturer: None; Manufacturer: Texas Instruments; SizeZ_mm: 0.8; ChType: N; Value2: 2.4 nC; Value1: 0.02; VdsMax_V: 30V; SizeX_mm: 2; Vgs_V: 20V; Value: 30V; Rdson45_ohm: 0.029; SizeArea_mm2: 4; AEC Category: Q101; IdsMax_A: 22A; SizeAreaWB_mm2: 9; U/M: EA; QgTyp_nC: 2.4
Q14 = CMP-0067551-1: as Q6 on sheet PROC219_Pilot_Interface
R88 R90-R93 R95 R99 R101 R103 = CMP-0026658-1: as R70-R72 on sheet PROC219_Pilot_Interface
R89 = CMP-0026017-3: RES, 14.7 k, 1%, 0.063 W, AEC-Q200 Grade 0, 0402; Manufacturer: Vishay-Dale; Power_W: 63mW; TempCo: 100 ppm/C; Value_Code: 14k7; Value: 14.7k; EIA_Code: E96; SizeX_mm: 1; SizeY_mm: 0.5; SizeZ_mm: 0.6; Value2: 0.063W; AEC Qualified: Y; VDC_V: 50V; AEC Category: Q200; AEC Grade: 0
R94 R107 = CMP-0026878-3: RES, 220, 5%, 0.063 W, AEC-Q200 Grade 0, 0402; Manufacturer: Vishay-Dale; Power_W: 63mW; TempCo: 200 ppm/C; Value_Code: 220R; Value: 220; EIA_Code: E24; SizeX_mm: 1; SizeY_mm: 0.5; SizeZ_mm: 0.6; Value2: 0.063W; AEC Qualified: Y; VDC_V: 50V; AEC Category: Q200; AEC Grade: 0
R96 = CMP-0026700-1: as R42-R45 on sheet PROC219_PLC
R97 R104 = CMP-0018797-2: as R73 on sheet PROC219_GBT
R98 R105 = CMP-0019763-2: RES, 200, 0.1%, 0.125 W, 0805; Manufacturer: Yageo America; Power_W: 125mW; TempCo: 25 ppm/C; Value_Code: 200R; U/M: EA; Value: 200; EIA_Code: E192; SizeX_mm: 2; SizeY_mm: 1.25; SizeZ_mm: 1.45; Value2: 0.125W; SizeArea_mm2: 2.5; VDC_V: 150V; AEC Category: Q200
R100 = CMP-0026919-5: as R79 on sheet PROC219_GBT
R102 = CMP-0026721-1: as R84 on sheet PROC219_GBT
R106 = CMP-0026449-2: as R64 on sheet PROC219_Pilot_Interface
SW3 = CMP-10038-000009-1: as SW1 on sheet PROC219_Pilot_Interface
TP25-TP29 = CMP-0003825-1: 1mm Test Point, SMT; Manufacturer: Any
U14 = CMP-0120107-1: 60-V, 100-mΩ, Single-Channel Smart High-Side Switch; Manufacturer: Texas Instruments; Part Number: TPS281C100DNTR; SizeZ_mm: 0.8mm; AEC Qualified: No; Max Supply Voltage: 60V; Min Supply Voltage: 6V; Nominal Supply Current: 0.98-1mA; Number Of Drivers: 1; Standoff Height: 0mm; TaMax_C: +125°C; TaMin_C: -40°C; TJmax_C: +150°C; Turn Off Delay Time: 35us; Turn On Delay Time: 25us
U15 = CMP-0860894-1: Low power, small size comparator with push-pull output, DCK0005A (SOT-SC70-5); Alternate Manufacturer: Texas Instruments; Alternate PartNumber: TLV7011DCKT; CompType: IC; SizeZ_mm: 1.1; SizeY_mm: 2; AEC Qualified: N; AEC Category: Q200; SizeX_mm: 2.1; SizeAreaWB_mm2: 9.3; SizeArea_mm2: 4.2; Rating: Catalog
